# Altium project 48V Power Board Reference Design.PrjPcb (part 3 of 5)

## Sheet Motor Drivers.SchDoc
size 431 x 279 mm; Date: Not shown in title block; ApprovedBy: Not shown in title block; CheckedBy: Not shown in title block; Author: Not shown in title block; CompanyName: Not shown in title block; Engineer: Not shown in title block; Organization: Not shown in title block; Address1: Not shown in title block; Address2: Not shown in title block; Address3: Not shown in title block; Address4: Not shown in title block; DocumentNumber: 10; Revision: Use project parameter SCH_Rev; SheetNumber: 6; SheetTotal: 15; PageSetup: Record=PageOptions¦CenterHorizontal=True¦CenterVertical=True¦PrintScale=1.00¦XCorrection=1.00¦YCorrection=1.00¦PrintKind=0¦BorderSize=5000000¦LeftOffset=0¦BottomOffset=0¦Orientation=2¦PaperLength=1000¦PaperWidth=1000¦Scale=100¦PaperSource=15¦PrintQuality=600¦MediaType=1¦DitherType=10¦PaperKind=Letter¦PrintScaleMode=1
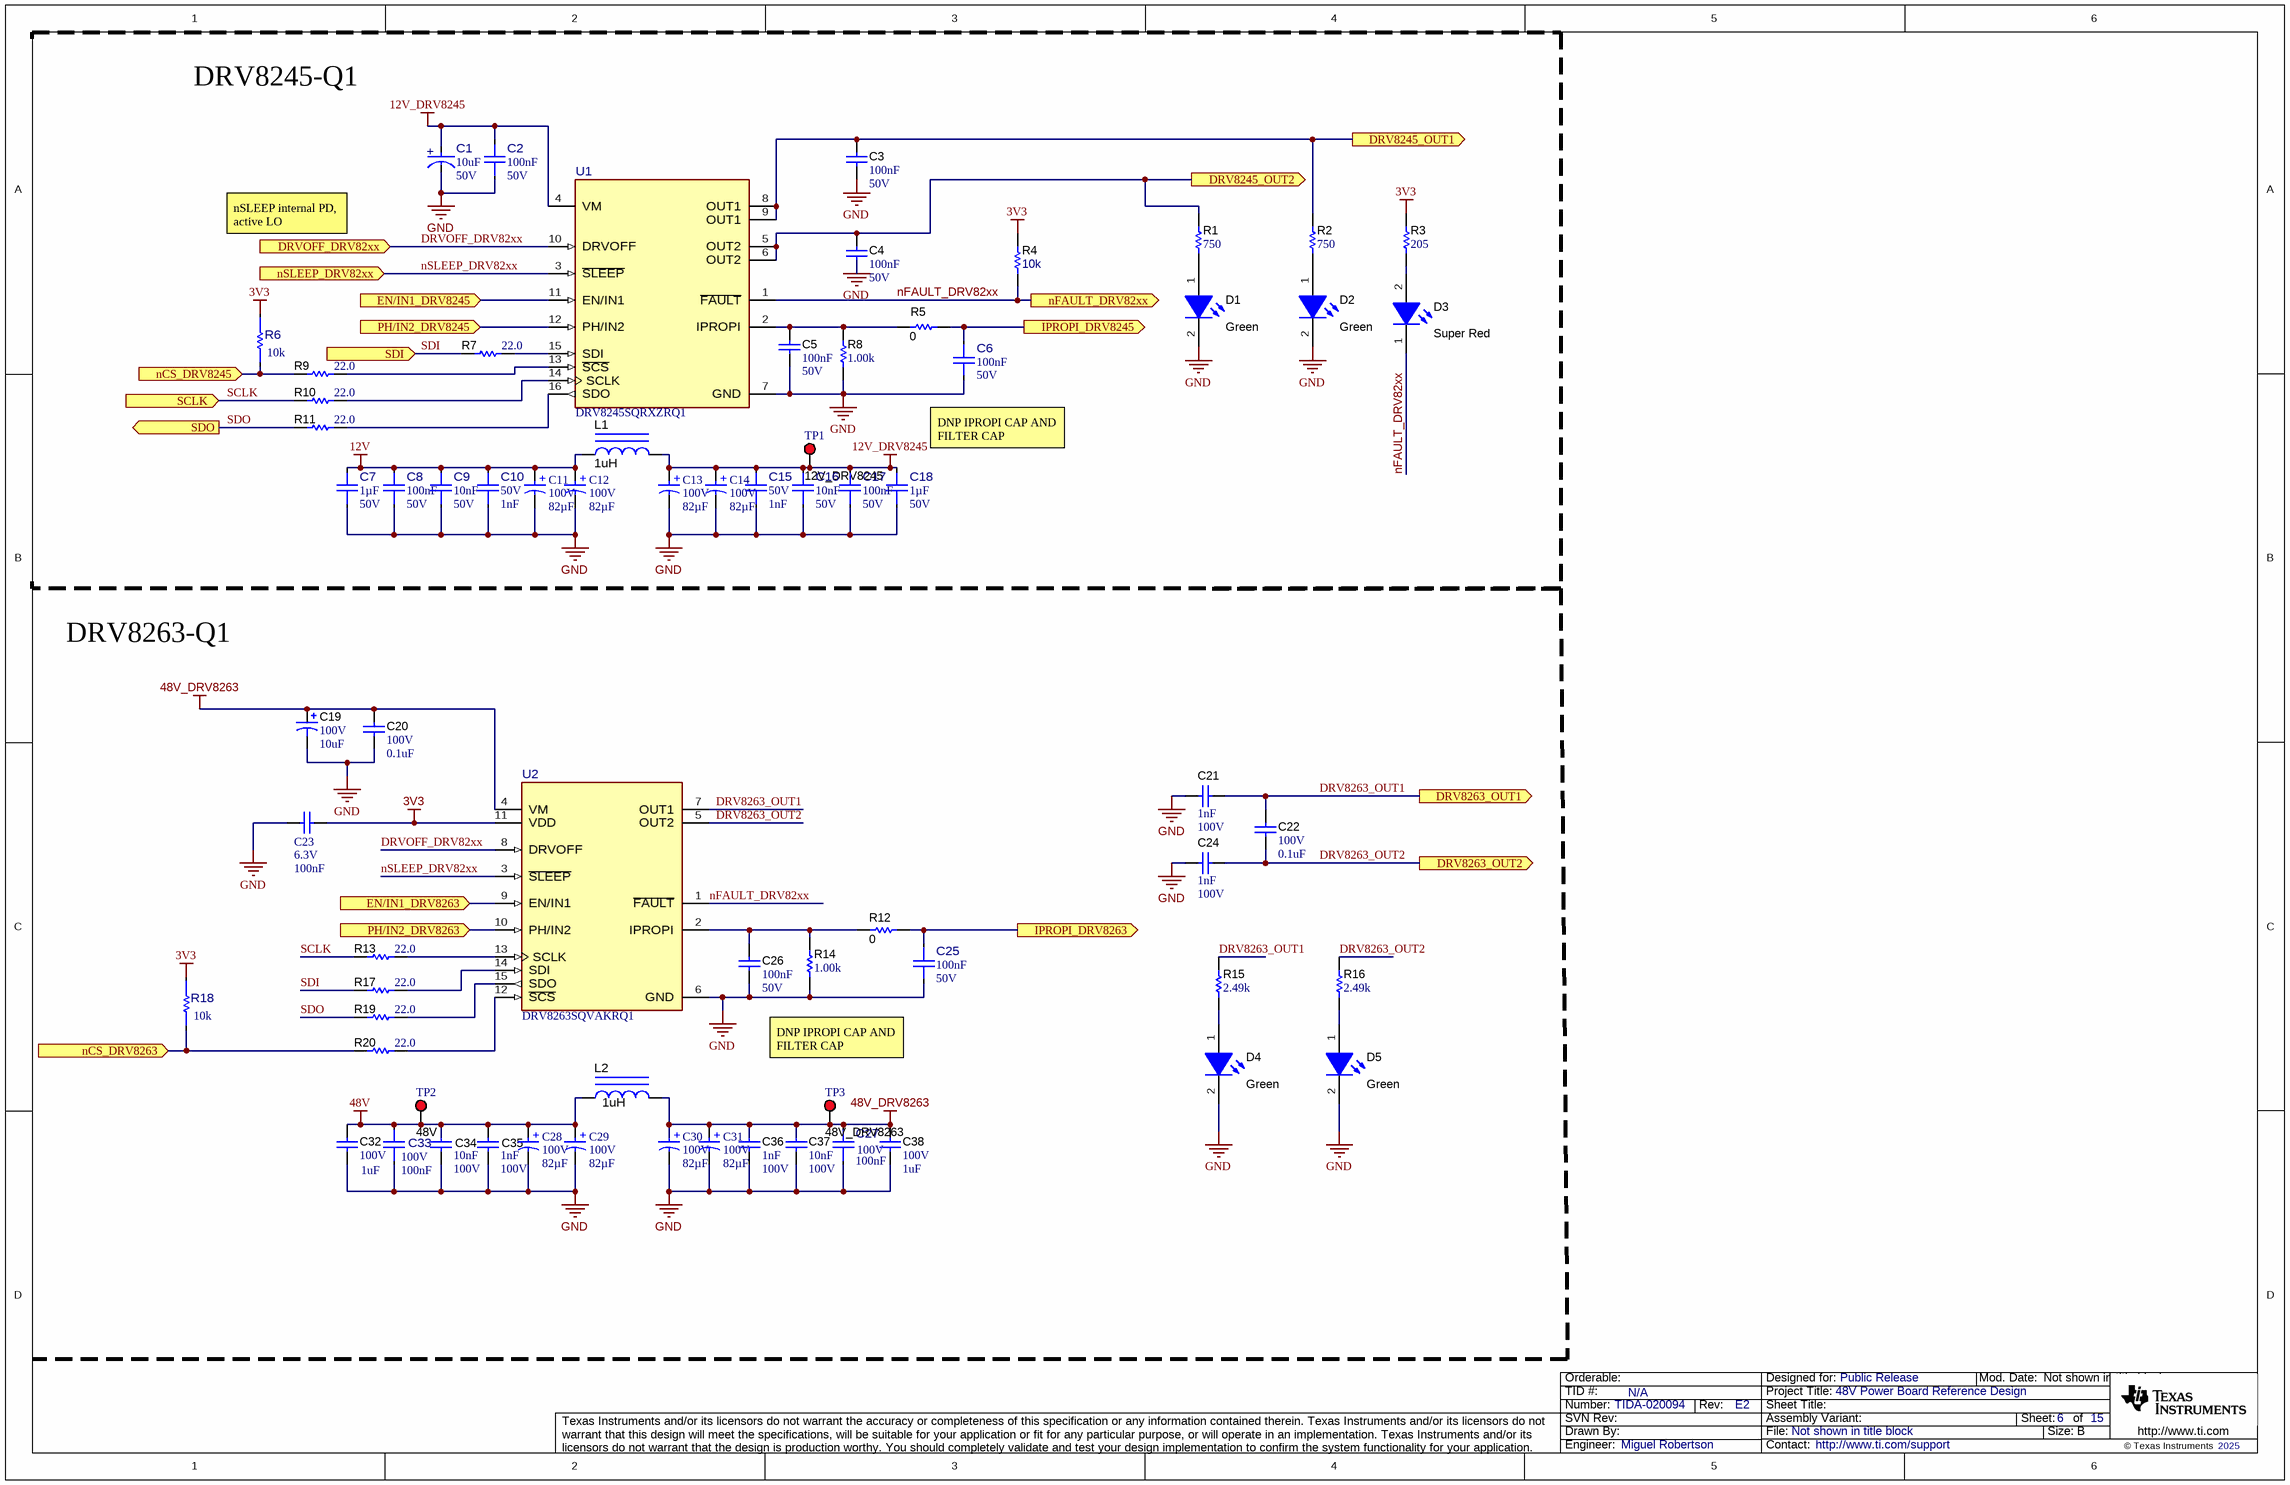
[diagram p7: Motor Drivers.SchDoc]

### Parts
C1  ValueDisplayed: 10uF  VDC_V: 50V  [FP-EEE-HA1H100P_RADIAL-MFG]  (hidden comment: EEE-HA1H100P)
C2  Cap_F: 100nF  VDC_V: 50V  [FP-06035C104J4Z2A_0603-MFG]  (hidden comment: 06035C104J4Z2A)
C3  Cap_F: 100nF  VDC_V: 50V  [0603]  (hidden comment: 885012206095)
C4  Cap_F: 100nF  VDC_V: 50V  [0603]  (hidden comment: 885012206095)
C5  Cap_F: 100nF  VDC_V: 50V  [0603]  (hidden comment: 885012206095)
C6  Cap_F: 100nF  VDC_V: 50V  [FP-C0603C104J5RAC7867_0603-MFG]  (hidden comment: C0603C104J5RAC7867)
C7  Cap_F: 1µF  VDC_V: 50V  [FP-CL10B105KB9VPJC_0603-MFG]  (hidden comment: CL10B105KB9VPJC)
C8  Cap_F: 100nF  VDC_V: 50V  [FP-06035C104J4Z2A_0603-MFG]  (hidden comment: 06035C104J4Z2A)
C9  Cap_F: 10nF  VDC_V: 50V  [FP-GCE188R71H103KA01D_0603-MFG]  (hidden comment: GCE188R71H103KA01D)
C10  VDC_V: 50V  Cap_F: 1nF  [FP-CGA3E2X7R1H102K080AA_0603-MFG]  (hidden comment: CGA3E2X7R1H102K080AA)
C11  Cap_F: 82µF  Rated Voltage (DC): 100V  [WCAP-ATUL_D10H20]  (hidden comment: 860040875004)
C12  Cap_F: 82µF  Rated Voltage (DC): 100V  [WCAP-ATUL_D10H20]  (hidden comment: 860040875004)
C13  Cap_F: 82µF  Rated Voltage (DC): 100V  [WCAP-ATUL_D10H20]  (hidden comment: 860040875004)
C14  Cap_F: 82µF  Rated Voltage (DC): 100V  [WCAP-ATUL_D10H20]  (hidden comment: 860040875004)
C15  VDC_V: 50V  Cap_F: 1nF  [FP-CGA3E2X7R1H102K080AA_0603-MFG]  (hidden comment: CGA3E2X7R1H102K080AA)
C16  Cap_F: 10nF  VDC_V: 50V  [FP-GCE188R71H103KA01D_0603-MFG]  (hidden comment: GCE188R71H103KA01D)
C17  Cap_F: 100nF  VDC_V: 50V  [FP-06035C104J4Z2A_0603-MFG]  (hidden comment: 06035C104J4Z2A)
C18  Cap_F: 1µF  VDC_V: 50V  [FP-CL10B105KB9VPJC_0603-MFG]  (hidden comment: CL10B105KB9VPJC)
C19  VDC_V: 100V  ValueDisplayed: 10uF  [SM_RADIAL_E]  (hidden comment: EEE-2AA100UP)
C20  VDC_V: 100V  ValueDisplayed: 0.1uF  [1206_180]  (hidden comment: C3216X7R2A104K160AA)
C21  Cap_F: 1nF  VDC_V: 100V  [0603]  (hidden comment: CGA3E2X7R2A102K080AA)
C22  VDC_V: 100V  ValueDisplayed: 0.1uF  [1206_180]  (hidden comment: C3216X7R2A104K160AA)
C23  Cap_F: 100nF  Rated Voltage (DC): 6.3V  [WCAP-CSGP_0402_L1W0.5H0.5]  (hidden comment: 885012105001)
C24  Cap_F: 1nF  VDC_V: 100V  [0603]  (hidden comment: CGA3E2X7R2A102K080AA)
C25  Cap_F: 100nF  VDC_V: 50V  [FP-C0603C104J5RAC7867_0603-MFG]  (hidden comment: C0603C104J5RAC7867)
C26  Cap_F: 100nF  VDC_V: 50V  [0603]  (hidden comment: 885012206095)
C27  VDC_V: 100V  Cap_F: 100nF  [FP-885012206120_0603-MFG]  (hidden comment: 885012206120)
C28  Cap_F: 82µF  Rated Voltage (DC): 100V  [WCAP-ATUL_D10H20]  (hidden comment: 860040875004)
C29  Cap_F: 82µF  Rated Voltage (DC): 100V  [WCAP-ATUL_D10H20]  (hidden comment: 860040875004)
C30  Cap_F: 82µF  Rated Voltage (DC): 100V  [WCAP-ATUL_D10H20]  (hidden comment: 860040875004)
C31  Cap_F: 82µF  Rated Voltage (DC): 100V  [WCAP-ATUL_D10H20]  (hidden comment: 860040875004)
C32  VDC_V: 100V  ValueDisplayed: 1uF  [0805_HV]  (hidden comment: C2012X7S2A105K125AB)
C33  VDC_V: 100V  Cap_F: 100nF  [FP-885012206120_0603-MFG]  (hidden comment: 885012206120)
C34  Cap_F: 10nF  VDC_V: 100V  [0603]  (hidden comment: 885012206114)
C35  Cap_F: 1nF  VDC_V: 100V  [0603]  (hidden comment: 06031C102KAT2A)
C36  Cap_F: 1nF  VDC_V: 100V  [0603]  (hidden comment: 06031C102KAT2A)
C37  Cap_F: 10nF  VDC_V: 100V  [0603]  (hidden comment: 885012206114)
C38  VDC_V: 100V  ValueDisplayed: 1uF  [0805_HV]  (hidden comment: C2012X7S2A105K125AB)
D1  value Green  [LTST-C191_Green]  (hidden comment: LTST-C191KGKT)
D2  value Green  [LTST-C191_Green]  (hidden comment: LTST-C191KGKT)
D3  value Super Red  [WL-SMCW_RED]  (hidden comment: 150060SS75000)
D4  value Green  [LTST-C191_Green]  (hidden comment: LTST-C191KGKT)
D5  value Green  [LTST-C191_Green]  (hidden comment: LTST-C191KGKT)
L1  ValueDisplayed: 1uH  [WE-HCC_1210]  (hidden comment: 7443320100)
L2  ValueDisplayed: 1uH  [WE-HCC_1210]  (hidden comment: 7443320100)
R1  ValueDisplayed: 750  [0603]  (hidden comment: RC0603FR-07750RL)
R2  ValueDisplayed: 750  [0603]  (hidden comment: RC0603FR-07750RL)
R3  ValueDisplayed: 205  [0603]  (hidden comment: RC0603FR-07205RL)
R4  ValueDisplayed: 10k  [0603]  (hidden comment: RC0603JR-0710KL)
R5  value 0  [0603L]  (hidden comment: Resistor)
R6  value 10k  [FP-RC0402JR-0710KL_0402-MFG]  (hidden comment: RC0402JR-0710KL)
R7  ValueDisplayed: 22.0  [0201]  (hidden comment: RC0201FR-0722RL)
R8  ValueDisplayed: 1.00k  [0603]  (hidden comment: CRCW06031K00FKEA)
R9  ValueDisplayed: 22.0  [0201]  (hidden comment: RC0201FR-0722RL)
R10  ValueDisplayed: 22.0  [0201]  (hidden comment: RC0201FR-0722RL)
R11  ValueDisplayed: 22.0  [0201]  (hidden comment: RC0201FR-0722RL)
R12  value 0  [0603L]  (hidden comment: Resistor)
R13  ValueDisplayed: 22.0  [0201]  (hidden comment: RC0201FR-0722RL)
R14  ValueDisplayed: 1.00k  [0603]  (hidden comment: RC0603FR-071KL)
R15  ValueDisplayed: 2.49k  [0603]  (hidden comment: RC0603FR-072K49L)
R16  ValueDisplayed: 2.49k  [0603]  (hidden comment: RC0603FR-072K49L)
R17  ValueDisplayed: 22.0  [0201]  (hidden comment: RC0201FR-0722RL)
R18  value 10k  [FP-RC0402JR-0710KL_0402-MFG]  (hidden comment: RC0402JR-0710KL)
R19  ValueDisplayed: 22.0  [0201]  (hidden comment: RC0201FR-0722RL)
R20  ValueDisplayed: 22.0  [0201]  (hidden comment: RC0201FR-0722RL)
TP1  12V_DRV8245  [Keystone5010]
TP2  48V  [Keystone5010]
TP3  48V_DRV8263  [Keystone5010]
U1  DRV8245SQRXZRQ1  [RXZ0016A-MFG]
U2  DRV8263SQVAKRQ1  [VAK0015A-MFG]

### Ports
DRV8245_OUT1 (out), DRV8245_OUT2 (out), DRV8263_OUT1 (out), DRV8263_OUT2 (out), DRVOFF_DRV82xx (in), EN/IN1_DRV8245 (in), EN/IN1_DRV8263 (in), IPROPI_DRV8245 (out), IPROPI_DRV8263 (out), nCS_DRV8245 (in), nCS_DRV8263 (in), nFAULT_DRV82xx (out), nSLEEP_DRV82xx (in), PH/IN2_DRV8245 (in), PH/IN2_DRV8263 (in), SCLK (in), SDI (in), SDO (out)

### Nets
3V3: C23.1 R3.2 R4.2 R6.1 R18.1 U2.11(VDD)
12V: C7.2 C8.2 C9.2 C10.2 C11.1(P) C12.1(P) L1.1
12V_DRV8245: C1.2(ANODE) C2.2 C13.1(P) C14.1(P) C15.2 C16.2 C17.2 C18.2 L1.2 TP1.1 U1.4(VM)
48V: C28.1(P) C29.1(P) C32.2 C33.2 C34.2 C35.1 L2.1 TP2.1
48V_DRV8263: C19.1(+) C20.1 C27.2 C30.1(P) C31.1(P) C36.1 C37.2 C38.2 L2.2 TP3.1 U2.4(VM)
GND: C1.1(CATHODE) C2.1 C3.1 C4.1 C5.1 C6.2 C7.1 C8.1 C9.1 C10.1 C11.2(N) C12.2(N) C13.2(N) C14.2(N) C15.1 C16.1 C17.1 C18.1 C19.2(-) C20.2 C21.1 C23.2 C24.1 C25.2 C26.1 C27.1 C28.2(N) C29.2(N) C30.2(N) C31.2(N) C32.1 C33.1 C34.1 C35.2 C36.2 C37.1 C38.1 D1.2(K) D2.2(K) D4.2(K) D5.2(K) R8.1 R14.1 U1.7(GND) U2.6(GND)
DRV8245_OUT1: C3.2 R2.2 U1.8(OUT1) U1.9(OUT1) ; port DRV8245_OUT1
DRV8245_OUT2: C4.2 R1.2 U1.5(OUT2) U1.6(OUT2) ; port DRV8245_OUT2
DRV8263_OUT1: C21.2 C22.1 R15.2 U2.7(OUT1) ; port DRV8263_OUT1
DRV8263_OUT2: C22.2 C24.2 R16.2 U2.5(OUT2) ; port DRV8263_OUT2
DRVOFF_DRV82xx: U1.10(DRVOFF) U2.8(DRVOFF) ; port DRVOFF_DRV82xx
EN/IN1_DRV8245: U1.11(EN/IN1) ; port EN/IN1_DRV8245
EN/IN1_DRV8263: U2.9(EN/IN1) ; port EN/IN1_DRV8263
IPROPI_DRV8245: C6.1 R5.2 ; port IPROPI_DRV8245
IPROPI_DRV8263: C25.1 R12.2 ; port IPROPI_DRV8263
nCS_DRV8245: R6.2 R9.1 ; port nCS_DRV8245
nCS_DRV8263: R18.2 R20.1 ; port nCS_DRV8263
nFAULT_DRV82xx: D3.1(K) R4.1 U1.1(~{FAULT}) U2.1(~{FAULT}) ; port nFAULT_DRV82xx
nSLEEP_DRV82xx: U1.3(~{SLEEP}) U2.3(~{SLEEP}) ; port nSLEEP_DRV82xx
PH/IN2_DRV8245: U1.12(PH/IN2) ; port PH/IN2_DRV8245
PH/IN2_DRV8263: U2.10(PH/IN2) ; port PH/IN2_DRV8263
SCLK: R10.1 R13.1 ; port SCLK
SDI: R7.1 R17.1 ; port SDI  [project net ]
SDO: R11.1 R19.1 ; port SDO
NetC5_2: C5.2 R5.1 R8.2 U1.2(IPROPI)
NetC26_2: C26.2 R12.1 R14.2 U2.2(IPROPI)
NetD1_1: D1.1(A) R1.1
NetD2_1: D2.1(A) R2.1
NetD3_2: D3.2(A) R3.1
NetD4_1: D4.1(A) R15.1
NetD5_1: D5.1(A) R16.1
NetR7_2: R7.2 U1.15(SDI)
NetR9_2: R9.2 U1.13(~{SCS})
NetR10_2: R10.2 U1.14(SCLK)
NetR11_2: R11.2 U1.16(SDO)
NetR13_2: R13.2 U2.13(SCLK)
NetR17_2: R17.2 U2.14(SDI)
NetR19_2: R19.2 U2.15(SDO)
NetR20_2: R20.2 U2.12(~{SCS})

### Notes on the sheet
- DRV8245-Q1
- nSLEEP internal PD, active LO
- DNP IPROPI CAP AND FILTER CAP
- DRV8263-Q1

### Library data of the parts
C1 = CMP-0094833-1: 10 µF 50 V Aluminum Electrolytic Capacitors Radial, Can - SMD - 1000 Hrs @ 105°C; Manufacturer: Panasonic Electronic Components; AEC Grade: Grade 2; IRMS_A: 35mA; SizeZ_mm: 5.5mm; Leakage Current: 5uA; Tolerance_%: 20%; Dissipation Factor: 12%; Value: 10µF; Life: 1000Hours; AEC Qualified: Yes
C2 C8 C17 = CMP-0094511-1: 0.1 µF ±5% 50V Ceramic Capacitor X7R 0603 (1608 Metric); Manufacturer: KYOCERA AVX; AEC Qualified: Yes; AEC Grade: NA; ValueDisplayed: 0.1uF; Value: 100nF; TempCo: 15%; SizeZ_mm: 0.9mm
C3-C5 C26 = CMP-0006837-2: CAP, CERM, 0.1 uF, 50 V, +/- 10%, X7R, 0603; Manufacturer: Wurth Elektronik; TaMin_C: -55°C; Polarized: N; SizeAreaWB_mm2: 4.68; Value1: Unknown; U/M: EA; Value: 0.1uF; TaMax_C: 125°C; SizeZ_mm: 1; SizeX_mm: 1.6; SizeY_mm: 0.8; SizeArea_mm2: 1.28; AEC Category: Q200
C6 C25 = CMP-0122528-1: Cap Ceramic 0.1uF 50V X7R 5% SMD 1.6 x 0.8 mm 125 C Paper T/R; Manufacturer: KEMET; AEC Qualified: No; SizeZ_mm: 0.95mm; TempCo: 15%; Value: 100nF
C7 C18 = CMP-0122257-1: 1 µF ±10% 50V Ceramic Capacitor X7R 0603 (1608 Metric); Manufacturer: Samsung; AEC Grade: Grade 1; AEC Qualified: Yes; SizeZ_mm: 1mm; TempCo: 15%; ValueDisplayed: 1uF; Value: 1µF
C9 C16 = CMP-0095668-2: Ceramic Capacitor 10nF ±10% 50V X7R 0603; Manufacturer: Murata; SizeZ_mm: 0.9mm; TempCo: 15%; AEC Grade: Grade 1; AEC Qualified: Yes
C10 C15 = CMP-0094874-1: Cap Ceramic 1nF 50V X7R 10% Pad SMD 0603 +125°C Automotive T/R; Manufacturer: TDK; Tolerance_%: 0.1%; AEC Qualified: Yes; SizeZ_mm: 1.1mm; AEC Grade: Grade 1; TempCo: 0.15
C11-C14 C28-C31 = CMP-0102582-1: WCAP-ATUL Aluminum Electrolytic Capacitor, Radial, THT, D10 x H20mm, 82µF, 100V; Manufacturer: Wurth Elektronik; Capacitance Tolerance: 20%; Dissipation Factor: 9%; Endurance: 7000h; Leakage Current: 82uA; Ripple Current: 600mA; Technical Reference: ATDF200820M100DSPAAG000
C19 = CMP-0011164-2: CAP, AL, 10 uF, 100 V, +/- 20%, AEC-Q200 Grade 3, SMD; Manufacturer: Panasonic; TaMin_C: -40°C; Polarized: Y; SizeAreaWB_mm2: 118.45; Value1: Unknown; U/M: EA; Value: 10uF; TaMax_C: 85°C; SizeZ_mm: 6.2; SizeX_mm: 9.5; SizeY_mm: 8.3; Cap_Case: 8.0x6.0mm; SizeArea_mm2: 78.85; CompType: Capacitor; Cap_F: 10µF; IRMS_A: 50mA; AEC Grade: 3; AEC Category: Q200
C20 C22 = CMP-0008709-2: CAP, CERM, 0.1 uF, 100 V, +/- 10%, X7R, 1206; Manufacturer: TDK; TaMin_C: -55°C; ESR_ohm: 30.343m; Polarized: N; SizeAreaWB_mm2: 10.92; Value1: 0.030343 ohm; U/M: EA; Value: 0.1uF; TaMax_C: 125°C; SizeZ_mm: 1.8; SizeX_mm: 3.2; SizeY_mm: 1.6; SizeArea_mm2: 5.12; Cap_F: 100nF; IRMS_A: 1.338A; AEC Category: Q200
C21 C24 = CMP-0007081-4: CAP, CERM, 1000 pF, 100 V, +/- 10%, X7R, AEC-Q200 Grade 1, 0603; Manufacturer: TDK; TaMin_C: -55°C; ESR_ohm: 1.97137; Polarized: N; SizeAreaWB_mm2: 4.68; Value1: 1.97137 ohm; U/M: EA; Value: 1000pF; TaMax_C: 125°C; SizeZ_mm: 1; SizeX_mm: 1.6; SizeY_mm: 0.8; SizeArea_mm2: 1.28; AEC Qualified: Y; IRMS_A: 305.705mA; AEC Category: Q200
C23 = CMP-0115207-1: WCAP-CSGP Multilayer Ceramic Chip Capacitor, General Purpose, size 0402, X5R, 100nF, 6.3VDC; Manufacturer: Wurth Elektronik; Capacitance Tolerance: +/-20%; Dissipation Factor: 10%; Insulation Resistance: 1GOhm; Technical Reference: X5R0402104M6R3DFCT10000
C27 C33 = CMP-0097294-1: 0.1 µF ±10% 100V Ceramic Capacitor X7R 0603 (1608 Metric); Manufacturer: Wurth Electronics; TempCo: 15%; SizeZ_mm: 0.87mm; Value: 100nF; AEC Qualified: No
C32 C38 = CMP-0007891-2: CAP, CERM, 1 uF, 100 V, +/- 10%, X7S, 0805; Manufacturer: TDK; TaMin_C: -55°C; ESR_ohm: 8.255m; Polarized: N; SizeAreaWB_mm2: 6.75; Value1: 0.008255 ohm; U/M: EA; Value: 1uF; TaMax_C: 125°C; SizeZ_mm: 1.45; SizeX_mm: 2; SizeY_mm: 1.25; Cap_Case: 0805; SizeArea_mm2: 2.5; Cap_F: 1µF; IRMS_A: 2.27442A; AEC Category: Q200
C34 C37 = CMP-0079993-1: CAP, CERM, 0.01 µF, 100 V,+/- 10%, X7R, 0603; Manufacturer: Wurth Elektronik; TaMin_C: -55°C; Polarized: N; SizeAreaWB_mm2: 4.68; U/M: EA; Value: 0.01uF; TaMax_C: 105°C; SizeZ_mm: 1; SizeX_mm: 1.6; SizeY_mm: 0.8; SizeArea_mm2: 1.28; AEC Category: Q200; ValueDisplayed: 0.01µF
C35 C36 = CMP-0006724-5: CAP, CERM, 1000 pF, 100 V, +/- 10%, X7R, 0603; Manufacturer: AVX; TaMin_C: -55°C; ESR_ohm: 2.76d; Polarized: N; SizeAreaWB_mm2: 4.68; Value1: 0.276 ohm; U/M: EA; Value: 1000pF; TaMax_C: 125°C; SizeZ_mm: 1; SizeX_mm: 1.6; SizeY_mm: 0.8; SizeArea_mm2: 1.28; AEC Category: Q200
D1 D2 D4 D5 = CMP-0078478-1: LED, Green, SMD; Manufacturer: Lite-On; Io_A: 30mA; Power_TotalModule: 75mW; Green_Lifecycle: Not Set; Vr_V: 5V; Tjmax_C: 85°C; Green_REACh: Incomplete; Value1: 0.075W; Angle: 130; Ir_A: 10µA; Vf_V: 2V; Type: AlInGaP
D3 = CMP-0002893-1: LED, Super Red, SMD; Manufacturer: Wurth Elektronik; Io_A: 20mA; Value1: W; U/M: EA; Vf_V: 1.9V; Type: AlInGaP
L1 L2 = CMP-0063986-1: Inductor, Shielded Drum Core, Ferrite, 1 uH, 24 A, 0.0012 ohm, SMD; Manufacturer: Wurth Elektronik; Isat: 32A @ 30% inductance drop; Irms: 24A @ 50C rise; Green_Lifecycle: Active; SizeAreaWB_mm2: 188.94; DCR_ohm: 1.2m; Green_REACh: Passed; Value: 1uH; Imax_A: 24A; SizeZ_mm: 10; SizeX_mm: 12.1; SizeY_mm: 11.4; SizeArea_mm2: 137.94; Ind_H: 1µH; AEC Category: Q200
R1 R2 = CMP-0023266-5: RES, 750, 1%, 0.1 W, 0603; Manufacturer: Yageo; Power_W: 100mW; TempCo: 100 ppm/C; Value_Code: 750R; Value: 750; EIA_Code: E96; SizeX_mm: 1.6; SizeY_mm: 0.8; SizeZ_mm: 1; Value2: 0.1W; SizeArea_mm2: 1.28; AEC Qualified: N; VDC_V: 75V; AEC Category: Q200; SizeAreaWB_mm2: 4.68
R3 = CMP-0022904-5: RES, 205, 1%, 0.1 W, 0603; Manufacturer: Yageo; Power_W: 100mW; TempCo: 100 ppm/C; Value_Code: 205R; Value: 205; EIA_Code: E96; SizeX_mm: 1.6; SizeY_mm: 0.8; SizeZ_mm: 1; Value2: 0.1W; SizeArea_mm2: 1.28; AEC Qualified: N; VDC_V: 75V; AEC Category: Q200; SizeAreaWB_mm2: 4.68
R4 = CMP-0025886-3: RES, 10 k, 5%, 0.1 W, 0603; Manufacturer: Yageo America; Power_W: 100mW; TempCo: 100 ppm/C; Value_Code: 10k0; U/M: EA; Value: 10k; EIA_Code: E24; SizeX_mm: 1.6; SizeY_mm: 0.8; SizeZ_mm: 1; Value2: 0.1W; SizeArea_mm2: 1.28; VDC_V: 50V; AEC Category: Q200
R5 R12 = CMP-0025697-4: RES, 0, 5%, 0.1 W, AEC-Q200 Grade 0, 0603; PartNumber: CRCW06030000Z0EA; Manufacturer: Vishay-Dale; Value_Code: 0000; Power_W: 100mW; Value2: 0.1W; VDC_V: 75V; TempCo: 200 ppm/C; EIA_Code: E24; AEC Category: Q200; AEC Qualified: Y; SizeArea_mm2: 1.28; SizeX_mm: 1.6; SizeY_mm: 0.8; SizeZ_mm: 1
R6 R18 = CMP-0094798-1: Res Thick Film 0402 10K Ohm 5% 0.063W(1/16W) ±100ppm/C Pad SMD T/R; Manufacturer: YAGEO; AEC Qualified: No; Category Cd01000Bfc2916C6: Single Components; SizeZ_mm: 0.4mm; VDC_V: 50V; Category 5C6A91606D4187Ad: Resistors; TempCo: 100ppm/°C; Power_W: 63mW; Category 7542B8484461Ae85: Passive Components
R7 R9-R11 R13 R17 R19 R20 = CMP-0027500-1: RES, 22.0, 1%, 0.05 W, 0201; Manufacturer: Yageo America; Power_W: 50mW; TempCo: 200 ppm/C; Value_Code: 22R0; U/M: EA; Value: 22.0; Res_ohm: 22; SizeX_mm: 0.6; SizeY_mm: 0.3; SizeZ_mm: 0.26; Value2: 0.05W; SizeArea_mm2: 0.18; AEC Qualified: N; VDC_V: 25V; AEC Category: Q200
R8 = CMP-0022109-5: RES, 1.00 k, 1%, 0.1 W, AEC-Q200 Grade 0, 0603; Manufacturer: Vishay-Dale; Power_W: 100mW; TempCo: 100 ppm/C; Value_Code: 1k00; Value: 1.00k; EIA_Code: E96; Res_ohm: 1k; SizeX_mm: 1.6; SizeY_mm: 0.8; SizeZ_mm: 1; Value2: 0.1W; SizeArea_mm2: 1.28; AEC Qualified: Y; VDC_V: 75V; AEC Category: Q200; AEC Grade: 0
R14 = CMP-0022895-5: RES, 1.00 k, 1%, 0.1 W, 0603; Manufacturer: Yageo; Power_W: 100mW; TempCo: 100 ppm/C; Value_Code: 1k00; Value: 1.00k; EIA_Code: E96; Res_ohm: 1k; SizeX_mm: 1.6; SizeY_mm: 0.8; SizeZ_mm: 1; Value2: 0.1W; SizeArea_mm2: 1.28; AEC Qualified: N; VDC_V: 75V; AEC Category: Q200; SizeAreaWB_mm2: 4.68
R15 R16 = CMP-0022990-5: RES, 2.49 k, 1%, 0.1 W, 0603; Manufacturer: Yageo; Power_W: 100mW; TempCo: 100 ppm/C; Value_Code: 2k49; Value: 2.49k; EIA_Code: E96; SizeX_mm: 1.6; SizeY_mm: 0.8; SizeZ_mm: 1; Value2: 0.1W; SizeArea_mm2: 1.28; AEC Qualified: N; VDC_V: 75V; AEC Category: Q200; SizeAreaWB_mm2: 4.68
TP1-TP3 = CMP-0055147-2: Test Point, Multipurpose, Red, TH; Manufacturer: Keystone Electronics; CT: TRUE; ContactFinish: Silver; Green_Lifecycle: Active; CNHeader: FALSE; Green_REACh: Passed
U1 = CMP-0095863-1: Automotive H-Bridge Driver with Integrated Current Sense and Diagnostics; Manufacturer: Texas Instruments; Max Supply Voltage: 35V; Number Of Outputs: 2; Min Supply Voltage: 4.5V; TaMax_C: +125°C; AEC Qualified: Yes; TJmax_C: +150°C; Nominal Supply Current: 10mA; Switching Frequency: 25kHz; Standoff Height: 0mm; SizeZ_mm: 1mm; AEC Grade: Grade 1; TaMin_C: -40°C
U2 = CMP-0121932-1: Automotive 65-V H-Bridge Driver with Integrated Current Sense and Diagnostics; Manufacturer: Texas Instruments; SizeZ_mm: 1mm; AEC Qualified: Yes; AEC Grade: Grade 1; Max Supply Voltage: 65V; Min Supply Voltage: 3V; Motor Type: Brushed; Nominal Supply Current: 3mA; Number Of Outputs: 2; Standoff Height: 0mm; Switching Frequency: 0-100kHz; TaMax_C: +125°C; TaMin_C: -40°C; TJmax_C: +150°C

## Sheet 12V E-Fuse.SchDoc
size 431 x 279 mm; Date: Not shown in title block; ApprovedBy: Not shown in title block; CheckedBy: Not shown in title block; Author: Not shown in title block; CompanyName: Not shown in title block; Engineer: Not shown in title block; Organization: Not shown in title block; Address1: Not shown in title block; Address2: Not shown in title block; Address3: Not shown in title block; Address4: Not shown in title block; DocumentNumber: 13; Revision: Use project parameter SCH_Rev; SheetNumber: 4; SheetTotal: 15; PageSetup: Record=PageOptions¦CenterHorizontal=True¦CenterVertical=True¦PrintScale=1.00¦XCorrection=1.00¦YCorrection=1.00¦PrintKind=0¦BorderSize=5000000¦LeftOffset=0¦BottomOffset=0¦Orientation=2¦PaperLength=1000¦PaperWidth=1000¦Scale=100¦PaperSource=15¦PrintQuality=600¦MediaType=1¦DitherType=10¦PaperKind=Letter¦PrintScaleMode=1
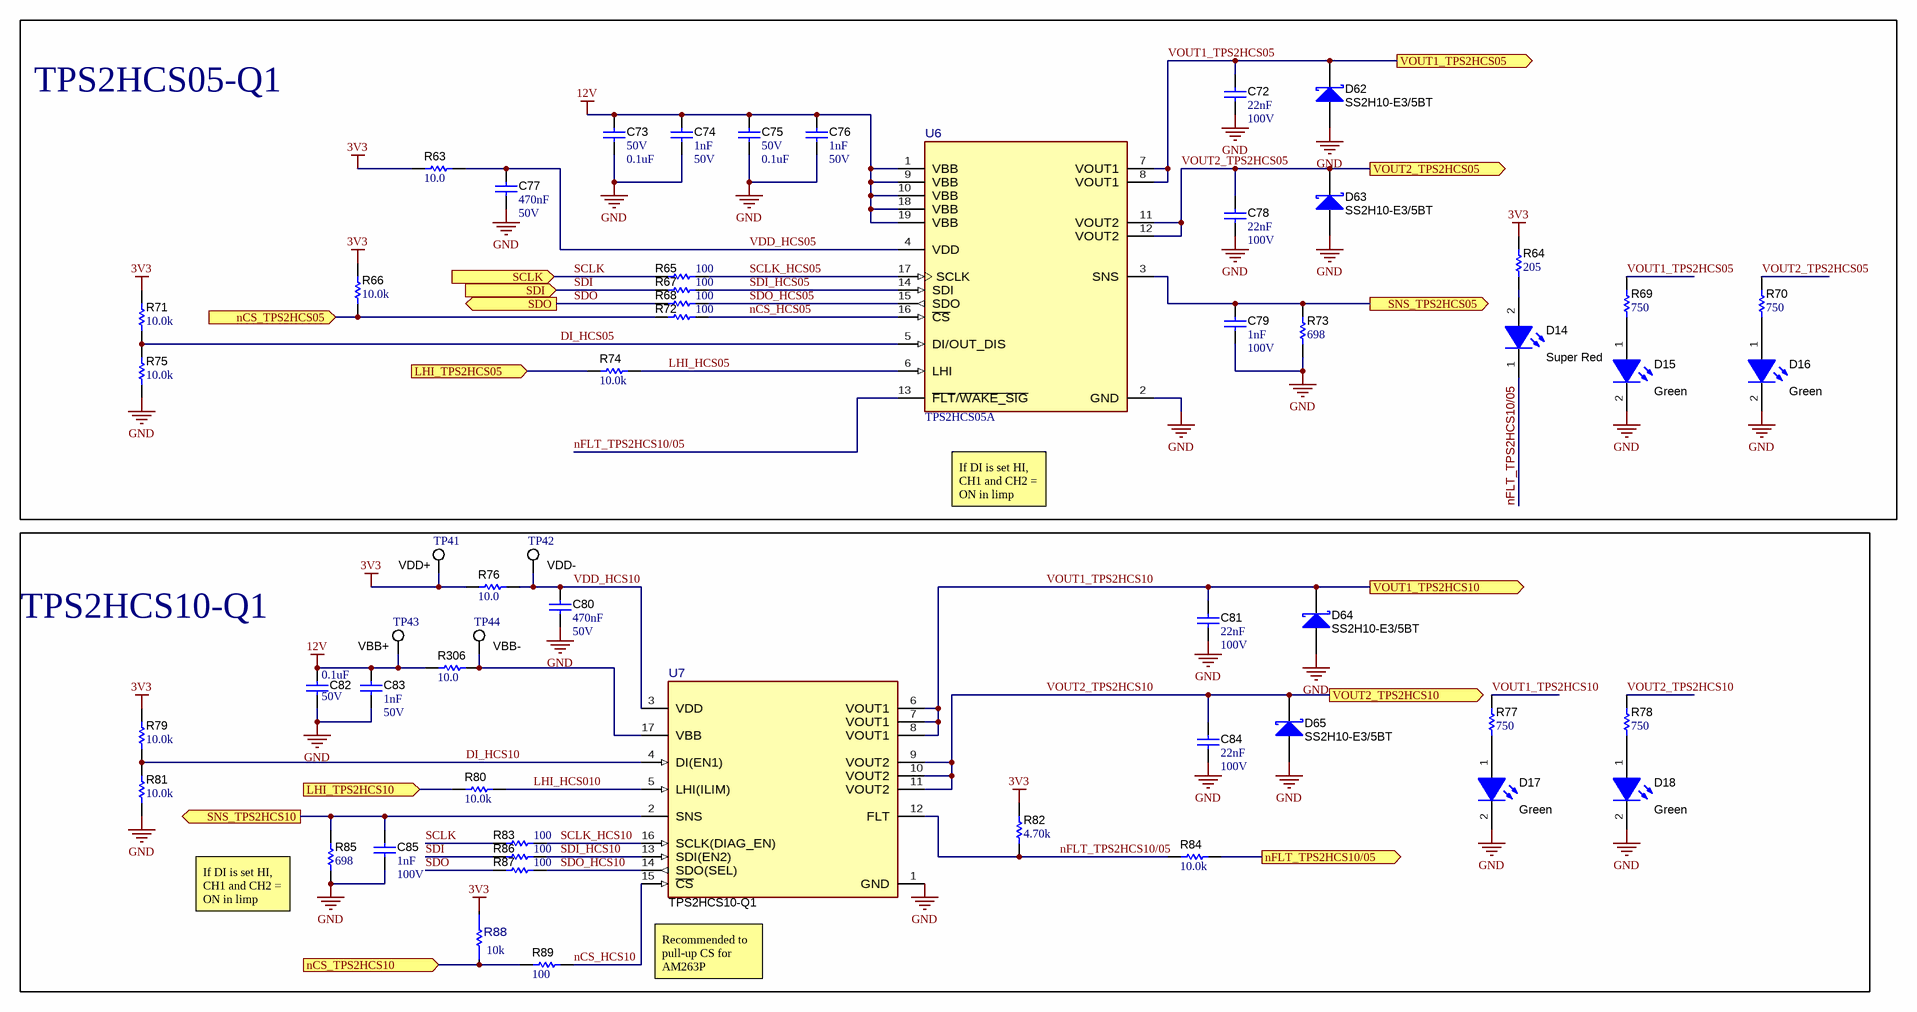
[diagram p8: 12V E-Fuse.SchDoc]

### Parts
C72  Cap_F: 22nF  VDC_V: 100V  [0603]  (hidden comment: CGA3E2X7R2A223K080AA)
C73  VDC_V: 50V  ValueDisplayed: 0.1uF  [0402]  (hidden comment: GCM155R71H104KE02D)
C74  Cap_F: 1nF  VDC_V: 50V  [0603]  (hidden comment: C0603X102K5RACTU)
C75  VDC_V: 50V  ValueDisplayed: 0.1uF  [0402]  (hidden comment: GCM155R71H104KE02D)
C76  Cap_F: 1nF  VDC_V: 50V  [0603]  (hidden comment: C0603X102K5RACTU)
C77  Cap_F: 470nF  VDC_V: 50V  [0603]  (hidden comment: C1608X7R1H474K080AC)
C78  Cap_F: 22nF  VDC_V: 100V  [0603]  (hidden comment: CGA3E2X7R2A223K080AA)
C79  Cap_F: 1nF  VDC_V: 100V  [0603]  (hidden comment: CGA3E2X7R2A102K080AA)
C80  Cap_F: 470nF  VDC_V: 50V  [0603]  (hidden comment: C1608X7R1H474K080AC)
C81  Cap_F: 22nF  VDC_V: 100V  [0603]  (hidden comment: CGA3E2X7R2A223K080AA)
C82  VDC_V: 50V  ValueDisplayed: 0.1uF  [0402]  (hidden comment: GCM155R71H104KE02D)
C83  Cap_F: 1nF  VDC_V: 50V  [0603]  (hidden comment: C0603X102K5RACTU)
C84  Cap_F: 22nF  VDC_V: 100V  [0603]  (hidden comment: CGA3E2X7R2A223K080AA)
C85  Cap_F: 1nF  VDC_V: 100V  [0603]  (hidden comment: CGA3E2X7R2A102K080AA)
D14  value Super Red  [WL-SMCW_RED]  (hidden comment: 150060SS75000)
D15  value Green  [LTST-C191_Green]  (hidden comment: LTST-C191KGKT)
D16  value Green  [LTST-C191_Green]  (hidden comment: LTST-C191KGKT)
D17  value Green  [LTST-C191_Green]  (hidden comment: LTST-C191KGKT)
D18  value Green  [LTST-C191_Green]  (hidden comment: LTST-C191KGKT)
D62  SS2H10-E3/5BT  [SMB]
D63  SS2H10-E3/5BT  [SMB]
D64  SS2H10-E3/5BT  [SMB]
D65  SS2H10-E3/5BT  [SMB]
R63  ValueDisplayed: 10.0  [0603]  (hidden comment: RC0603FR-0710RL)
R64  ValueDisplayed: 205  [0603]  (hidden comment: RC0603FR-07205RL)
R65  ValueDisplayed: 100  [0603]  (hidden comment: CRCW0603100RJNEA)
R66  ValueDisplayed: 10.0k  [0603]  (hidden comment: RMCF0603FT10K0)
R67  ValueDisplayed: 100  [0603]  (hidden comment: CRCW0603100RJNEA)
R68  ValueDisplayed: 100  [0603]  (hidden comment: CRCW0603100RJNEA)
R69  ValueDisplayed: 750  [0603]  (hidden comment: RC0603FR-07750RL)
R70  ValueDisplayed: 750  [0603]  (hidden comment: RC0603FR-07750RL)
R71  ValueDisplayed: 10.0k  [0603]  (hidden comment: RMCF0603FT10K0)
R72  ValueDisplayed: 100  [0603]  (hidden comment: CRCW0603100RJNEA)
R73  ValueDisplayed: 698  [0603]  (hidden comment: RC0603FR-07698RL)
R74  ValueDisplayed: 10.0k  [0603]  (hidden comment: RMCF0603FT10K0)
R75  ValueDisplayed: 10.0k  [0603]  (hidden comment: RMCF0603FT10K0)
R76  ValueDisplayed: 10.0  [0603]  (hidden comment: RC0603FR-0710RL)
R77  ValueDisplayed: 750  [0603]  (hidden comment: RC0603FR-07750RL)
R78  ValueDisplayed: 750  [0603]  (hidden comment: RC0603FR-07750RL)
R79  ValueDisplayed: 10.0k  [0603]  (hidden comment: RMCF0603FT10K0)
R80  ValueDisplayed: 10.0k  [0603]  (hidden comment: RMCF0603FT10K0)
R81  ValueDisplayed: 10.0k  [0603]  (hidden comment: RMCF0603FT10K0)
R82  ValueDisplayed: 4.70k  [0603]  (hidden comment: RC0603FR-074K7L)
R83  ValueDisplayed: 100  [0603]  (hidden comment: CRCW0603100RJNEA)
R84  ValueDisplayed: 10.0k  [0603]  (hidden comment: RMCF0603FT10K0)
R85  ValueDisplayed: 698  [0603]  (hidden comment: RC0603FR-07698RL)
R86  ValueDisplayed: 100  [0603]  (hidden comment: CRCW0603100RJNEA)
R87  ValueDisplayed: 100  [0603]  (hidden comment: CRCW0603100RJNEA)
R88  value 10k  [FP-RC0402JR-0710KL_0402-MFG]  (hidden comment: RC0402JR-0710KL)
R89  ValueDisplayed: 100  [0603]  (hidden comment: CRCW0603100RJNEA)
R306  ValueDisplayed: 10.0  [0603]  (hidden comment: RC0603FR-0710RL)
TP41  VDD+  [Keystone5012]
TP42  VDD-  [Keystone5012]
TP43  VBB+  [Keystone5012]
TP44  VBB-  [Keystone5012]
U6  TPS2HCS05A  [PWC0018A-MFG]
U7  TPS2HCS10-Q1  [PWP0016P-MFG]

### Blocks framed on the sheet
TPS2HCS05-Q1: C72-C79 D14-D16 D62 D63 R63-R75 U6
TPS2HCS10-Q1: C80-C85 D17 D18 D64 D65 R76-R89 R306 TP41-TP44 U7

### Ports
LHI_TPS2HCS05 (in), LHI_TPS2HCS10 (in), nCS_TPS2HCS05 (in), nCS_TPS2HCS10 (in), nFLT_TPS2HCS10/05 (out), SCLK (in), SDI (in), SDO (out), SNS_TPS2HCS05 (out), SNS_TPS2HCS10 (out), VOUT1_TPS2HCS05 (out), VOUT1_TPS2HCS10 (out), VOUT2_TPS2HCS05 (out), VOUT2_TPS2HCS10 (out)

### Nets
3V3: R63.1 R64.2 R66.2 R71.2 R76.1 R79.2 R82.2 R88.1 TP41.1
12V: C73.1 C74.1 C75.1 C76.1 C82.1 C83.1 R306.1 TP43.1 U6.1(VBB) U6.9(VBB) U6.10(VBB) U6.18(VBB) U6.19(VBB)
GND: C72.2 C73.2 C74.2 C75.2 C76.2 C77.2 C78.2 C79.2 C80.2 C81.2 C82.2 C83.2 C84.2 C85.2 D15.2(K) D16.2(K) D17.2(K) D18.2(K) D62.2(A) D63.2(A) D64.2(A) D65.2(A) R73.1 R75.2 R81.2 R85.1 U6.2(GND) U7.1(GND)
DI_HCS05: R71.1 R75.1 U6.5(DI/OUT_DIS)  [project net DI_HCS05_4]
DI_HCS10: R79.1 R81.1 U7.4(DI(EN1))  [project net DI_HCS10_4]
LHI_HCS05: R74.1 U6.6(LHI)  [project net LHI_HCS05_4]
LHI_HCS010: R80.1 U7.5(LHI(ILIM))  [project net LHI_HCS010_4]
LHI_TPS2HCS05: R74.2 ; port LHI_TPS2HCS05
LHI_TPS2HCS10: R80.2 ; port LHI_TPS2HCS10
nCS_HCS05: R72.2 U6.16(~{CS})  [project net nCS_HCS05_4]
nCS_HCS10: R89.2 U7.15(~{CS})  [project net nCS_HCS10_4]
nCS_TPS2HCS05: R66.1 R72.1 ; port nCS_TPS2HCS05
nCS_TPS2HCS10: R88.2 R89.1 ; port nCS_TPS2HCS10
nFLT_TPS2HCS10/05: D14.1(K) R82.1 R84.2 U6.13(~{FLT}/~{WAKE_SIG}) U7.12(FLT)  [project net nFLT_TPS2HCS10/05_4]
nFLT_TPS2HCS10/05: R84.1 ; port nFLT_TPS2HCS10/05  [a separate net that carries the same name]
SCLK: R65.1 R83.1 ; port SCLK
SCLK_HCS05: R65.2 U6.17(SCLK)  [project net SCLK_HCS05_4]
SCLK_HCS10: R83.2 U7.16(SCLK(DIAG_EN))  [project net SCLK_HCS10_4]
SDI: R67.1 R86.1 ; port SDI  [project net ]
SDI_HCS05: R67.2 U6.14(SDI)  [project net SDI_HCS05_4]
SDI_HCS10: R86.2 U7.13(SDI(EN2))  [project net SDI_HCS10_4]
SDO: R68.1 R87.1 ; port SDO
SDO_HCS05: R68.2 U6.15(SDO)  [project net SDO_HCS05_4]
SDO_HCS10: R87.2 U7.14(SDO(SEL))  [project net SDO_HCS10_4]
SNS_TPS2HCS05: C79.1 R73.2 U6.3(SNS) ; port SNS_TPS2HCS05
SNS_TPS2HCS10: C85.1 R85.2 U7.2(SNS) ; port SNS_TPS2HCS10
VDD_HCS05: C77.1 R63.2 U6.4(VDD)  [project net VDD_HCS05_4]
VDD_HCS10: C80.1 R76.2 TP42.1 U7.3(VDD)  [project net VDD_HCS10_4]
VOUT1_TPS2HCS05: C72.1 D62.1(K) R69.2 U6.7(VOUT1) U6.8(VOUT1) ; port VOUT1_TPS2HCS05
VOUT1_TPS2HCS10: C81.1 D64.1(K) R77.2 U7.6(VOUT1) U7.7(VOUT1) U7.8(VOUT1) ; port VOUT1_TPS2HCS10
VOUT2_TPS2HCS05: C78.1 D63.1(K) R70.2 U6.11(VOUT2) U6.12(VOUT2) ; port VOUT2_TPS2HCS05
VOUT2_TPS2HCS10: C84.1 D65.1(K) R78.2 U7.9(VOUT2) U7.10(VOUT2) U7.11(VOUT2) ; port VOUT2_TPS2HCS10
NetD14_2: D14.2(A) R64.1
NetD15_1: D15.1(A) R69.1
NetD16_1: D16.1(A) R70.1
NetD17_1: D17.1(A) R77.1
NetD18_1: D18.1(A) R78.1
NetR306_2: R306.2 TP44.1 U7.17(VBB)

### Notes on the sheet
- If DI is set HI, CH1 and CH2 = ON in limp home state
- (near R85) If DI is set HI, CH1 and CH2 = ON in limp home state
- (near U7) Recommended to pull-up CS for AM263P

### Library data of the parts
C72 C78 C81 C84 = CMP-0007086-4: CAP, CERM, 0.022 uF, 100 V, +/- 10%, X7R, AEC-Q200 Grade 1, 0603; Manufacturer: TDK; TaMin_C: -55°C; ESR_ohm: 83.542m; Polarized: N; SizeAreaWB_mm2: 4.68; Value1: 0.083542 ohm; U/M: EA; TaMax_C: 125°C; SizeZ_mm: 1; SizeX_mm: 1.6; SizeY_mm: 0.8; SizeArea_mm2: 1.28; AEC Qualified: Y; IRMS_A: 609.312mA; AEC Category: Q200
C73 C75 C82 = CMP-0006356-2: CAP, CERM, 0.1 uF, 50 V, +/- 10%, X7R, AEC-Q200 Grade 1, 0402; Manufacturer: MuRata; TaMin_C: -55°C; Polarized: N; SizeAreaWB_mm2: 3; Value1: Unknown; U/M: EA; Value: 0.1uF; TaMax_C: 125°C; SizeZ_mm: 0.6; SizeX_mm: 1; SizeY_mm: 0.5; AEC Qualified: Y; Cap_F: 100nF; AEC Category: Q200
C74 C76 C83 = CMP-0006976-5: CAP, CERM, 1000 pF, 50 V, +/- 10%, X7R, 0603; Manufacturer: Kemet; TaMin_C: -55°C; Polarized: N; SizeAreaWB_mm2: 4.68; Value1: Unknown; U/M: EA; Value: 1000pF; TaMax_C: 125°C; SizeZ_mm: 1; SizeX_mm: 1.6; SizeY_mm: 0.8; SizeArea_mm2: 1.28; AEC Category: Q200
C77 C80 = CMP-0007050-1: CAP, CERM, 0.47 uF, 50 V, +/- 10%, X7R, 0603; Manufacturer: TDK; TaMin_C: -55°C; ESR_ohm: 10.974m; Polarized: N; SizeAreaWB_mm2: 4.68; Value1: 0.010974 ohm; U/M: EA; Value: 0.47uF; TaMax_C: 125°C; SizeZ_mm: 1; SizeX_mm: 1.6; SizeY_mm: 0.8; SizeArea_mm2: 1.28; IRMS_A: 1.5748A; AEC Category: Q200
C79 C85 = CMP-0007081-4: CAP, CERM, 1000 pF, 100 V, +/- 10%, X7R, AEC-Q200 Grade 1, 0603; Manufacturer: TDK; TaMin_C: -55°C; ESR_ohm: 1.9714; Polarized: N; SizeAreaWB_mm2: 4.68; Value1: 1.97137 ohm; U/M: EA; Value: 1000pF; TaMax_C: 125°C; SizeZ_mm: 1; SizeX_mm: 1.6; SizeY_mm: 0.8; SizeArea_mm2: 1.28; AEC Qualified: Y; IRMS_A: 305.705mA; AEC Category: Q200
D14 = CMP-0002893-1: as D3 on sheet Motor Drivers
D15-D18 = CMP-0078478-1: as D1 on sheet Motor Drivers
D62-D65 = CMP-0028987-2: Diode, Schottky, 100 V, 2 A, SMB; Manufacturer: Vishay-Semiconductor; Vf_V: 790mV; AEC Qualified: N; SizeArea_mm2: 21.336; Value: 100V; SizeX_mm: 5.6; Value1: 2A; Value2: 0.79V; SizeZ_mm: 2.6; SizeAreaWB_mm2: 44.156; AEC Category: Q101; TJmax_C: 175°C; SizeY_mm: 3.81
R63 R76 R306 = CMP-0022751-4: RES, 10.0, 1%, 0.1 W, 0603; Manufacturer: Yageo; Power_W: 100mW; TempCo: 100 ppm/C; Value_Code: 10R0; Value: 10.0; EIA_Code: E96; Res_ohm: 10; SizeX_mm: 1.6; SizeY_mm: 0.8; SizeZ_mm: 1; Value2: 0.1W; SizeArea_mm2: 1.28; AEC Qualified: N; VDC_V: 75V; AEC Category: Q200; SizeAreaWB_mm2: 4.68
R64 = CMP-0022904-5: as R3 on sheet Motor Drivers
R65 R67 R68 R72 R83 R86 R87 R89 = CMP-0025700-3: RES, 100, 5%, 0.1 W, 0603; Manufacturer: Vishay-Dale; Power_W: 100mW; TempCo: 200 ppm/C; Value_Code: 100R; U/M: EA; Value: 100; EIA_Code: E24; SizeX_mm: 1.6; SizeY_mm: 0.8; SizeZ_mm: 1; Value2: 0.1W; SizeArea_mm2: 1.28; VDC_V: 75V; AEC Category: Q200
R66 R71 R74 R75 R79-R81 R84 = CMP-0023341-2: RES, 10.0 k, 1%, 0.1 W, AEC-Q200 Grade 0, 0603; Manufacturer: Stackpole Electronics Inc; Power_W: 100mW; TempCo: 100 ppm/C; Value_Code: 10k0; U/M: EA; Value: 10.0k; EIA_Code: E96; Res_ohm: 10k; SizeX_mm: 1.6; SizeY_mm: 0.8; SizeZ_mm: 1; Value2: 0.1W; SizeArea_mm2: 1.28; AEC Qualified: Y; VDC_V: 75V; AEC Grade: 0; AEC Category: Q200
R69 R70 R77 R78 = CMP-0023266-5: as R1 on sheet Motor Drivers
R73 R85 = CMP-0023243-5: RES, 698, 1%, 0.1 W, 0603; Manufacturer: Yageo; Power_W: 100mW; TempCo: 100 ppm/C; Value_Code: 698R; Value: 698; EIA_Code: E96; SizeX_mm: 1.6; SizeY_mm: 0.8; SizeZ_mm: 1; Value2: 0.1W; SizeArea_mm2: 1.28; AEC Qualified: N; VDC_V: 75V; AEC Category: Q200; SizeAreaWB_mm2: 4.68
R82 = CMP-0023153-5: RES, 4.70 k, 1%, 0.1 W, 0603; Manufacturer: Yageo; Power_W: 100mW; TempCo: 100 ppm/C; Value_Code: 4k70; Value: 4.70k; Res_ohm: 4.7k; SizeX_mm: 1.6; SizeY_mm: 0.8; SizeZ_mm: 1; Value2: 0.1W; SizeArea_mm2: 1.28; AEC Qualified: N; VDC_V: 75V; AEC Category: Q200; SizeAreaWB_mm2: 4.68
R88 = CMP-0094798-1: as R6 on sheet Motor Drivers
TP41-TP44 = CMP-0055149-1: Test Point, Multipurpose, White, TH; Manufacturer: Keystone; CNHeader: FALSE; Green_Lifecycle: Active; Green_REACh: Passed; ContactFinish: Silver; CT: TRUE
U6 = CMP-0124507-1: 5mΩ, Automotive Dual-Channel, SPI Controlled High-Side Switch with Integrated I2 t Wire Protection and low power mode; Manufacturer: Texas Instruments; SizeZ_mm: 1.2mm; AEC Qualified: Yes; AEC Grade: Grade 1; Max Supply Voltage: 18V; Min Supply Voltage: 6V; Nominal Supply Current: 2-4.9mA; Number Of Drivers: 2; Standoff Height: 0.05mm; TaMax_C: +125°C; TaMin_C: -40°C; TJmax_C: +150°C
U7 = CMP-0098417-1: Manufacturer: Texas Instruments; SizeZ_mm: 1.2mm; Standoff Height: 0.05mm

## Sheet Backbone_input2.SchDoc
size 431 x 279 mm; Date: Not shown in title block; ApprovedBy: Not shown in title block; CheckedBy: Not shown in title block; Author: Not shown in title block; CompanyName: Not shown in title block; Engineer: Not shown in title block; Organization: Not shown in title block; Address1: Not shown in title block; Address2: Not shown in title block; Address3: Not shown in title block; Address4: Not shown in title block; DocumentNumber: 4; Revision: Use project parameter SCH_Rev; SheetNumber: 3; SheetTotal: 15; PageSetup: Record=PageOptions¦CenterHorizontal=True¦CenterVertical=True¦PrintScale=1.00¦XCorrection=1.00¦YCorrection=1.00¦PrintKind=0¦BorderSize=5000000¦LeftOffset=0¦BottomOffset=0¦Orientation=2¦PaperLength=1000¦PaperWidth=1000¦Scale=100¦PaperSource=15¦PrintQuality=600¦MediaType=1¦DitherType=10¦PaperKind=Letter¦PrintScaleMode=1
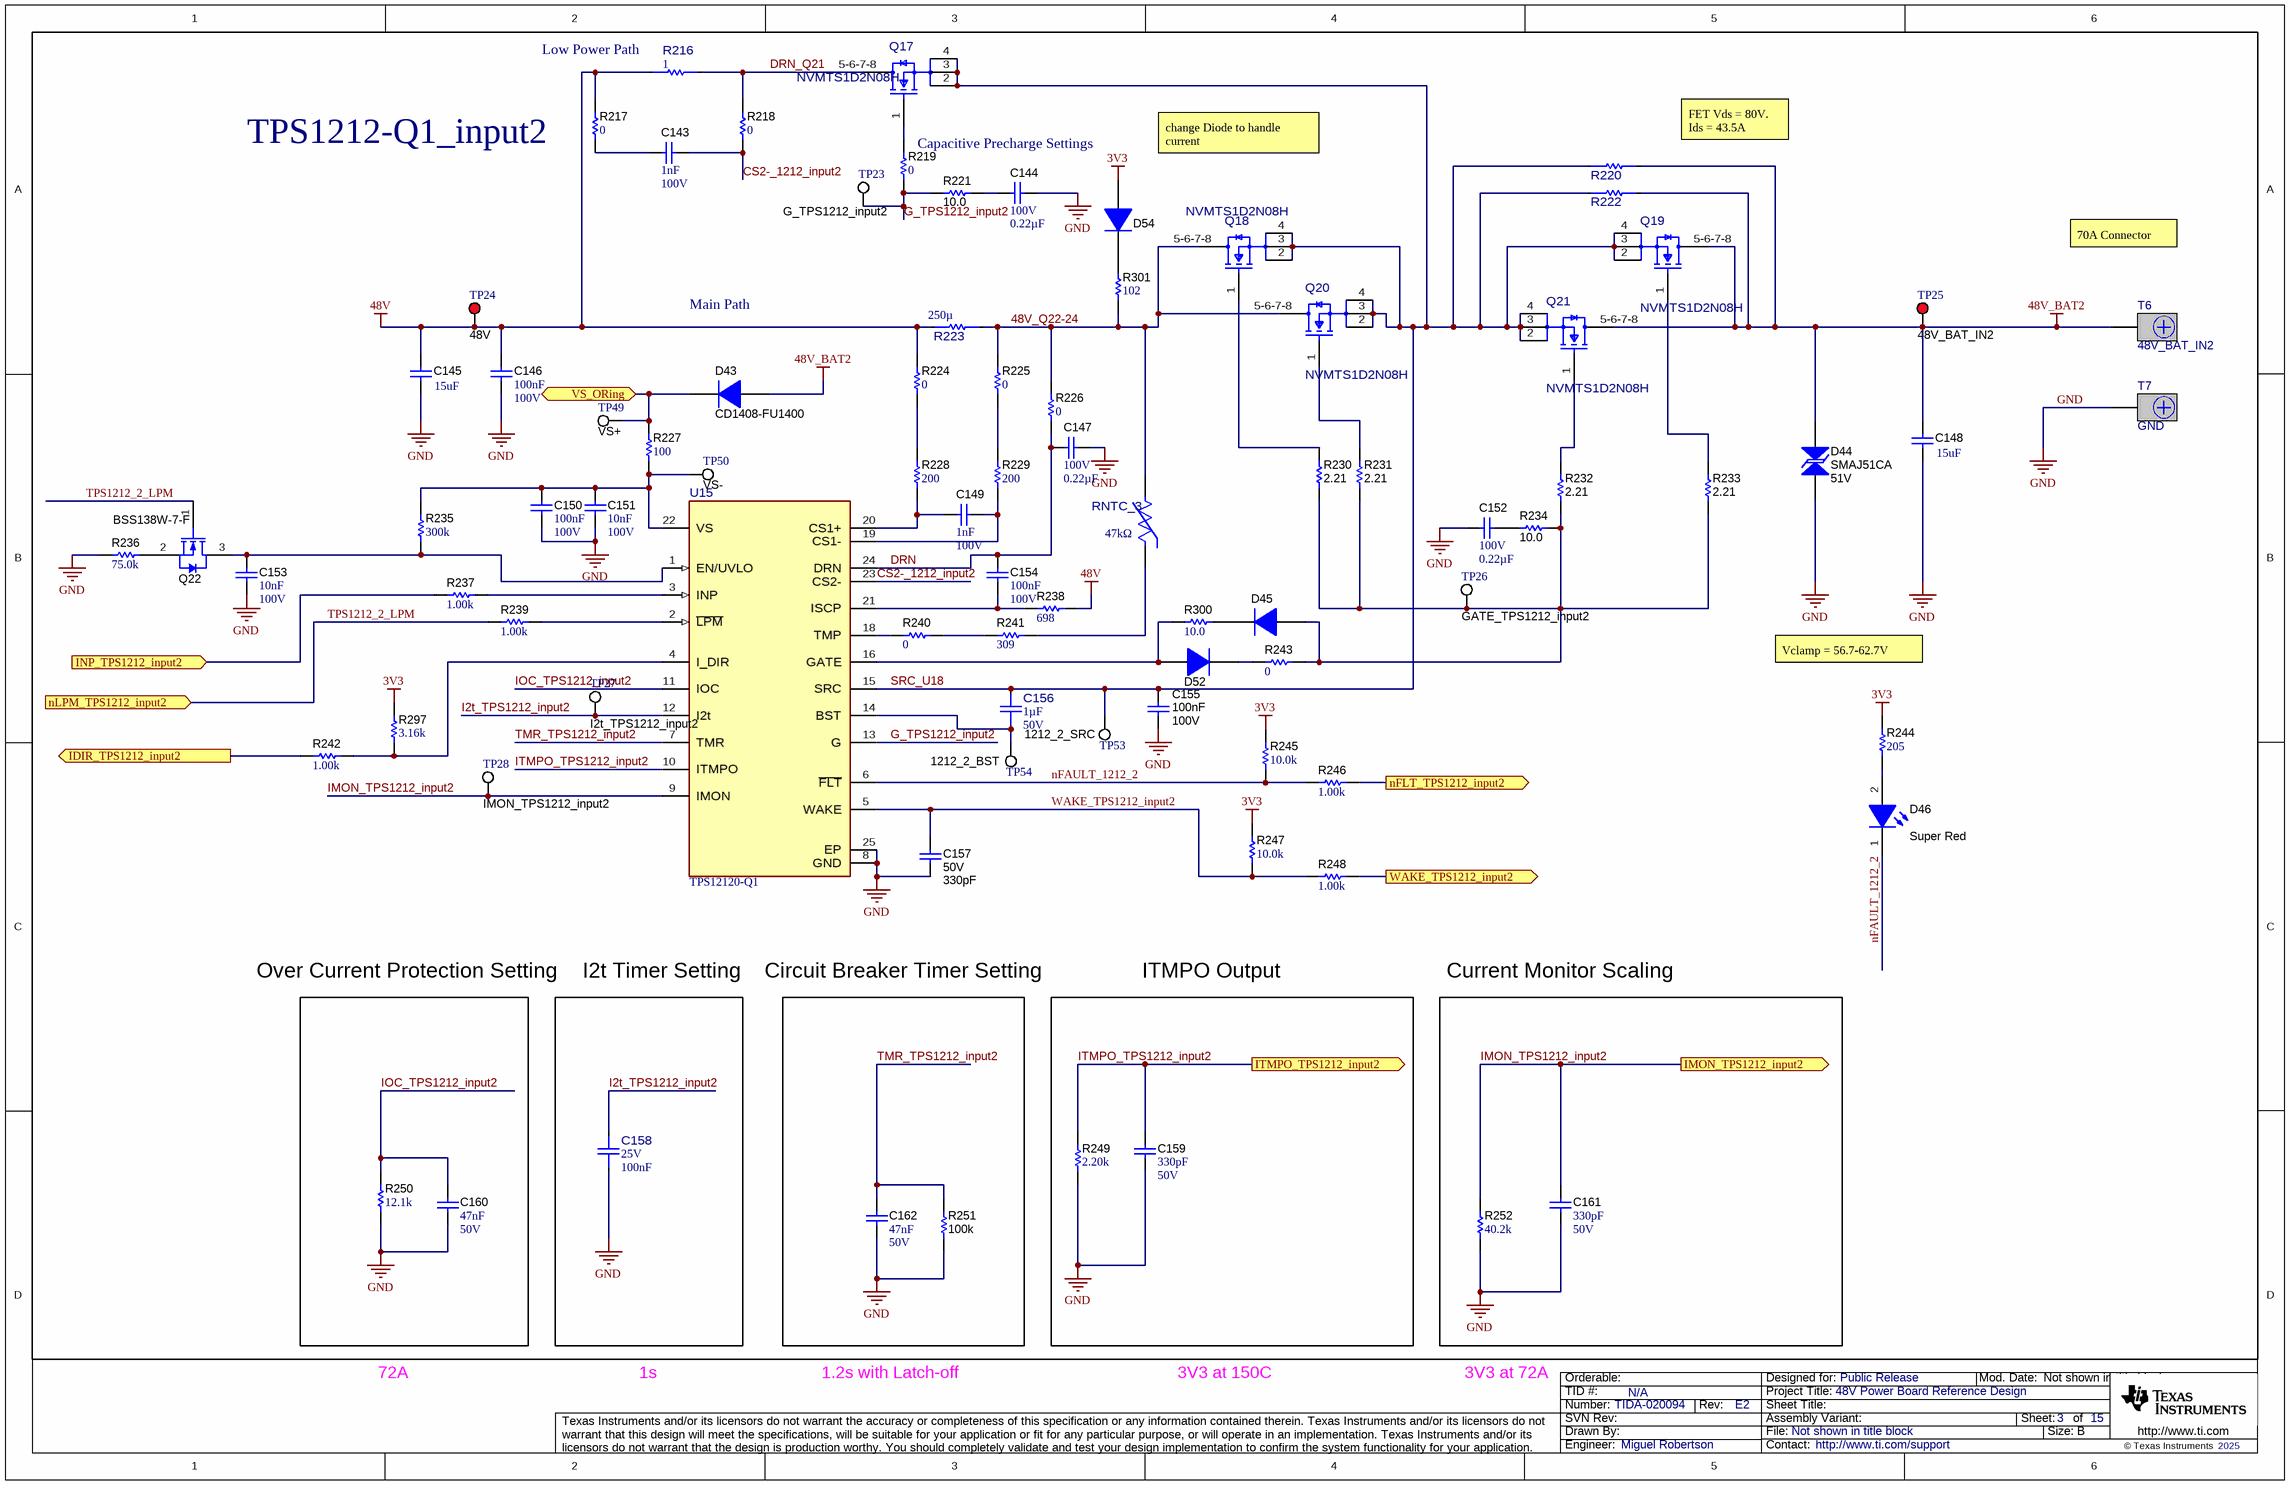
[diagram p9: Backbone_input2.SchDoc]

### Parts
C143  Cap_F: 1nF  VDC_V: 100V  [0603]  (hidden comment: CGA3E2X7R2A102K080AA)
C144  VDC_V: 100V  ValueDisplayed: 0.22µF  [0603]  (hidden comment: HMK107C7224MAHTE)
C145  ValueDisplayed: 15uF  [KCM55W]  (hidden comment: KCM55WR72A156MH01K)
C146  Cap_F: 100nF  VDC_V: 100V  [0603]  (hidden comment: HMK107B7104KAHT)
C147  VDC_V: 100V  ValueDisplayed: 0.22µF  [0603]  (hidden comment: HMK107C7224MAHTE)
C148  ValueDisplayed: 15uF  [KCM55W]  (hidden comment: KCM55WR72A156MH01K)
C149  Cap_F: 1nF  VDC_V: 100V  [0603]  (hidden comment: CGA3E2X7R2A102K080AA)
C150  Cap_F: 100nF  VDC_V: 100V  [0603]  (hidden comment: HMK107B7104KAHT)
C151  Cap_F: 10nF  VDC_V: 100V  [0603]  (hidden comment: CGA3E2X7R2A103K080AA)
C152  VDC_V: 100V  ValueDisplayed: 0.22µF  [0603]  (hidden comment: HMK107C7224MAHTE)
C153  Cap_F: 10nF  VDC_V: 100V  [0603]  (hidden comment: CGA3E2X7R2A103K080AA)
C154  Cap_F: 100nF  VDC_V: 100V  [0603]  (hidden comment: HMK107B7104KAHT)
C155  Cap_F: 100nF  VDC_V: 100V  [0805_HV]  (hidden comment: CGA4J2X7R2A104K125AA)
C156  Cap_F: 1µF  VDC_V: 50V  [FP-CL10B105KB9VPJC_0603-MFG]  (hidden comment: CL10B105KB9VPJC)
C157  VDC_V: 50V  ValueDisplayed: 330pF  [0402]  (hidden comment: GRM155R71H331KA01D)
C158  VDC_V: 25V  Cap_F: 100nF  [FP-GCJ188R71E104KA12D_0603-MFG]  (hidden comment: GCJ188R71E104KA12D)
C159  Cap_F: 330pF  VDC_V: 50V  [0603]  (hidden comment: C0603C331K5RACTU)
C160  Cap_F: 47nF  VDC_V: 50V  [0603]  (hidden comment: CGA3E2X7R1H473K080AA)
C161  Cap_F: 330pF  VDC_V: 50V  [0603]  (hidden comment: C0603C331K5RACTU)
C162  Cap_F: 47nF  VDC_V: 50V  [0603]  (hidden comment: CGA3E2X7R1H473K080AA)
D43  CD1408-FU1400  [Diode_1408]
D44  SMAJ51CA  value 51V  [SMA_Bi]
D45  1N4148W-TP  [SOD-123]  (value not drawn)
D46  value Super Red  [WL-SMCW_RED]  (hidden comment: 150060SS75000)
D52  1N4148W-TP  [SOD-123]  (value not drawn)
D54  1N4148W-TP  [SOD-123]  (value not drawn)
Q17  NVMTS1D2N08H  [FP-NVMTS1D2N08H_DFNW8-MFG]
Q18  NVMTS1D2N08H  [FP-NVMTS1D2N08H_DFNW8-MFG]
Q19  NVMTS1D2N08H  [FP-NVMTS1D2N08H_DFNW8-MFG]
Q20  NVMTS1D2N08H  [FP-NVMTS1D2N08H_DFNW8-MFG]
Q21  NVMTS1D2N08H  [FP-NVMTS1D2N08H_DFNW8-MFG]
Q22  BSS138W-7-F  [SOT-323]
R216  value 1  [FP-VMP-1R00-1.0-U_2010-MFG]  (hidden comment: VMP-1R00-1.0-U)
R217  ValueDisplayed: 0  [0603]  (hidden comment: CRCW06030000Z0EA)
R218  ValueDisplayed: 0  [0603]  (hidden comment: CRCW06030000Z0EA)
R219  ValueDisplayed: 0  [0603]  (hidden comment: CRCW06030000Z0EA)
R220  CSS2H-2512R-L500F  [FP-CSS2H-2512R-L500F_2512-MFG]  (value not drawn)
R221  ValueDisplayed: 10.0  [0805_HV]  (hidden comment: RC0805FR-0710RL)
R222  CSS2H-2512R-L500F  [FP-CSS2H-2512R-L500F_2512-MFG]  (value not drawn)
R223  value 250µ  [FP-HoLRS2512_2512-MFG]  (hidden comment: HoLRS2512-0.25mR-1%)
R224  ValueDisplayed: 0  [0603]  (hidden comment: CRCW06030000Z0EA)
R225  ValueDisplayed: 0  [0603]  (hidden comment: CRCW06030000Z0EA)
R226  ValueDisplayed: 0  [0603]  (hidden comment: CRCW06030000Z0EA)
R227  ValueDisplayed: 100  [0603]  (hidden comment: ERJ-3EKF1000V)
R228  ValueDisplayed: 200  [0603]  (hidden comment: RC0603FR-07200RL)
R229  ValueDisplayed: 200  [0603]  (hidden comment: RC0603FR-07200RL)
R230  ValueDisplayed: 2.21  [0603]  (hidden comment: RC0603FR-072R21L)
R231  ValueDisplayed: 2.21  [0603]  (hidden comment: RC0603FR-072R21L)
R232  ValueDisplayed: 2.21  [0603]  (hidden comment: RC0603FR-072R21L)
R233  ValueDisplayed: 2.21  [0603]  (hidden comment: RC0603FR-072R21L)
R234  ValueDisplayed: 10.0  [0805_HV]  (hidden comment: RC0805FR-0710RL)
R235  ValueDisplayed: 300k  [0603]  (hidden comment: RC0603FR-07300KL)
R236  ValueDisplayed: 75.0k  [0603]  (hidden comment: RC0603FR-0775KL)
R237  ValueDisplayed: 1.00k  [0603]  (hidden comment: RC0603FR-071KL)
R238  ValueDisplayed: 698  [0603]  (hidden comment: RC0603FR-07698RL)
R239  ValueDisplayed: 1.00k  [0603]  (hidden comment: RC0603FR-071KL)
R240  ValueDisplayed: 0  [0603]  (hidden comment: CRCW06030000Z0EA)
R241  ValueDisplayed: 309  [0603]  (hidden comment: RC0603FR-07309RL)
R242  ValueDisplayed: 1.00k  [0603]  (hidden comment: RC0603FR-071KL)
R243  ValueDisplayed: 0  [0603]  (hidden comment: CRCW06030000Z0EA)
R244  ValueDisplayed: 205  [0603]  (hidden comment: RC0603FR-07205RL)
R245  ValueDisplayed: 10.0k  [TNPW0603]  (hidden comment: TNPW060310K0BEEA)
R246  ValueDisplayed: 1.00k  [0603]  (hidden comment: RC0603FR-071KL)
R247  ValueDisplayed: 10.0k  [TNPW0603]  (hidden comment: TNPW060310K0BEEA)
R248  ValueDisplayed: 1.00k  [0603]  (hidden comment: RC0603FR-071KL)
R249  ValueDisplayed: 2.20k  [0603]  (hidden comment: RC0603FR-072K2L)
R250  ValueDisplayed: 12.1k  [0603]  (hidden comment: RC0603FR-0712K1L)
R251  ValueDisplayed: 100k  [0603]  (hidden comment: CRCW0603100KFKEA)
R252  ValueDisplayed: 40.2k  [0603]  (hidden comment: RC0603FR-0740K2L)
R297  ValueDisplayed: 3.16k  [0603]  (hidden comment: RC0603FR-073K16L)
R300  ValueDisplayed: 10.0  [0603]  (hidden comment: RC0603FR-0710RL)
R301  ValueDisplayed: 102  [0603]  (hidden comment: RC0603FR-07102RL)
RNTC_3  value 47kΩ  [FP-NCU18WB473J6SRB_0603-MFG]  (hidden comment: NCU18WB473J6SRB)
T6  48V_BAT_IN2  [Panduit_CXS70-14-C]
T7  GND  [Panduit_CXS70-14-C]
TP23  G_TPS1212_input2  [Keystone5012]
TP24  48V  [Keystone5010]
TP25  48V_BAT_IN2  [Keystone5010]
TP26  GATE_TPS1212_input2  [Keystone5012]
TP27  I2t_TPS1212_input2  [Keystone5012]
TP28  IMON_TPS1212_input2  [Keystone5012]
TP49  VS+  [Keystone5012]
TP50  VS-  [Keystone5012]
TP53  1212_2_SRC  [Keystone5012]
TP54  1212_2_BST  [Keystone5012]
U15  TPS12120-Q1  [RGE0023A-MFG]

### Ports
IDIR_TPS1212_input2 (out), IMON_TPS1212_input2 (out), INP_TPS1212_input2 (in), ITMPO_TPS1212_input2 (out), nFLT_TPS1212_input2 (out), nLPM_TPS1212_input2 (in), VS_ORing (bidir), WAKE_TPS1212_input2 (out)

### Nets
3V3: D54.2(A) R244.2 R245.2 R247.2 R297.2
48V: C145.1 C146.1 R216.1 R217.2 R223.1 R224.2 R238.2 TP24.1
48V_BAT2: C148.1 D43.2(A) D44.2 Q19.5-6-7-8(D) Q21.5-6-7-8(D) R220.2 R222.2 T6.1 TP25.1
GND: C144.1 C145.2 C146.2 C147.1 C148.2 C150.2 C151.2 C152.2 C153.2 C155.2 C157.2 C158.1 C159.2 C160.2 C161.2 C162.2 D44.1 R236.2 R249.1 R250.1 R251.1 R252.1 T7.1 U15.8(GND) U15.25(EP)
48V_Q22-24: Q18.5-6-7-8(D) Q20.5-6-7-8(D) R223.2 R225.2 R226.2 R301.1 RNTC_3.2  [project net 48V_Q22-24_3]
CS2-_1212_input2: C143.1 R218.1 U15.23(CS2-)  [project net CS2-_1212_input2_3]
DRN: C147.2 C154.1 R226.1 U15.24(DRN)  [project net DRN_3]
DRN_Q21: Q17.5-6-7-8(D) R216.2 R218.2  [project net DRN_Q21_3]
G_TPS1212_input2: R219.1 R221.2 TP23.1 U15.13(G)  [project net G_TPS1212_input2_3]
I2t_TPS1212_input2: C158.2 TP27.1 U15.12(I2t)  [project net I2t_TPS1212_input2_3]
IDIR_TPS1212_input2: R242.1 ; port IDIR_TPS1212_input2
IMON_TPS1212_input2: C161.1 R252.2 TP28.1 U15.9(IMON) ; port IMON_TPS1212_input2
INP_TPS1212_input2: R237.1 ; port INP_TPS1212_input2
IOC_TPS1212_input2: C160.1 R250.2 U15.11(IOC)  [project net IOC_TPS1212_input2_3]
ITMPO_TPS1212_input2: C159.1 R249.2 U15.10(ITMPO) ; port ITMPO_TPS1212_input2
nFAULT_1212_2: D46.1(K) R245.1 R246.1 U15.6(~{FLT})  [project net nFAULT_1212_2_3]
nFLT_TPS1212_input2: R246.2 ; port nFLT_TPS1212_input2
SRC_U18: C155.1 C156.2 Q17.2(S) Q17.3(S) Q17.4(S) Q18.2(S) Q18.3(S) Q18.4(S) Q19.2(S) Q19.3(S) Q19.4(S) Q20.2(S) Q20.3(S) Q20.4(S) Q21.2(S) Q21.3(S) Q21.4(S) R220.1 R222.1 TP53.1 U15.15(SRC)  [project net SRC_U18_3]
TMR_TPS1212_input2: C162.1 R251.2 U15.7(TMR)  [project net TMR_TPS1212_input2_3]
TPS1212_2_LPM: Q22.1(G) R239.1 ; port nLPM_TPS1212_input2  [project net nLPM_TPS1212_input2]
VS_ORing: D43.1(K) R227.2 TP49.1 ; port VS_ORing
WAKE_TPS1212_input2: C157.1 R247.1 R248.1 U15.5(WAKE)  [project net WAKE_TPS1212_input2_3]
WAKE_TPS1212_input2: R248.2 ; port WAKE_TPS1212_input2  [a separate net that carries the same name]
NetC143_2: C143.2 R217.1
NetC144_2: C144.2 R221.1
NetC149_1: C149.1 R229.1 U15.19(CS1-)
NetC149_2: C149.2 R228.1 U15.20(CS1+)
NetC150_1: C150.1 C151.1 R227.1 R235.2 TP50.1 U15.22(VS)
NetC152_1: C152.1 R234.1
NetC153_1: C153.1 Q22.3(D) R235.1 U15.1(EN/UVLO)
NetC154_2: C154.2 R238.1 U15.21(ISCP)
NetC156_1: C156.1 TP54.1 U15.14(BST)
NetD45_1: D45.1(K) R300.2
NetD45_2: D45.2(A) R230.1 R231.1 R232.1 R233.1 R234.2 R243.1 TP26.1
NetD46_2: D46.2(A) R244.1
NetD52_1: D52.1(K) R243.2
NetD52_2: D52.2(A) R300.1 U15.16(GATE)
NetD54_1: D54.1(K) R301.2
NetQ17_1: Q17.1(G) R219.2
NetQ18_1: Q18.1(G) R230.2
NetQ19_1: Q19.1(G) R233.2
NetQ20_1: Q20.1(G) R231.2
NetQ21_1: Q21.1(G) R232.2
NetQ22_2: Q22.2(S) R236.1
NetR224_1: R224.1 R228.2
NetR225_1: R225.1 R229.2
NetR237_2: R237.2 U15.3(INP)
NetR239_2: R239.2 U15.2(~{LPM})
NetR240_1: R240.1 R241.1
NetR240_2: R240.2 U15.18(TMP)
NetR241_2: R241.2 RNTC_3.1
NetR242_2: R242.2 R297.1 U15.4(I_DIR)

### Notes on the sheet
- (near R216) Low Power Path
- (near R217) TPS1212-Q1_input2
- (near R219) Capacitive Precharge Settings
- change Diode to handle current
- FET Vds = 80V. Ids = 43.5A
- 70A Connector
- Main Path
- Vclamp = 56.7-62.7V
- Over Current Protection Setting
- I2t Timer Setting
- Circuit Breaker Timer Setting
- ITMPO Output
- Current Monitor Scaling
- 72A
- 1s
- 1.2s with Latch-off
- 3V3 at 150C
- 3V3 at 72A

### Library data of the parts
C143 C149 = CMP-0007081-4: as C79 on sheet 12V E-Fuse
C144 C147 C152 = CMP-0077895-3: CAP, CERM, 0.22 µF, 100 V,+/- 20%, X7S, AEC-Q200 Grade 1, 0603; Manufacturer: Taiyo Yuden; TaMin_C: -55°C; Polarized: N; SizeAreaWB_mm2: 4.68; U/M: EA; Value: 0.22uF; TaMax_C: 125°C; SizeZ_mm: 1.0; SizeX_mm: 1.6; SizeY_mm: 0.8; SizeArea_mm2: 1.28; AEC Qualified: Y; Cap_F: 220nF; AEC Grade: 1; AEC Category: Q200
C145 C148 = CMP-0009477-2: CAP, CERM, 15 uF, 100 V, +/- 20%, X7R, Stacked 2220; Manufacturer: MuRata; TaMin_C: -55°C; Polarized: N; SizeAreaWB_mm2: 59.13; Value1: Unknown; U/M: EA; Value: 15uF; TaMax_C: 125°C; SizeZ_mm: 6.7; SizeX_mm: 6.1; SizeY_mm: 5.3; Cap_Case: 2220; Value2: 100V; SizeArea_mm2: 32.33; Cap_F: 15µF; AEC Category: Q200
C146 C150 C154 = CMP-0081011-1: CAP, CERM, 0.1 µF, 100 V,+/- 10%, X7R, AEC-Q200 Grade 1, 0603; Manufacturer: Taiyo Yuden; SizeAreaWB_mm2: 4.68; SizeArea_mm2: 1.28; AEC Qualified: Y; AEC Category: Q200; Value: 0.1uF; TaMax_C: 125°C; SizeZ_mm: 1; Polarized: N; TaMin_C: -55°C; SizeY_mm: 0.8; U/M: EA; SizeX_mm: 1.6; ValueDisplayed: 0.1µF
C151 C153 = CMP-0007082-4: CAP, CERM, 0.01 uF, 100 V, +/- 10%, X7R, AEC-Q200 Grade 1, 0603; Manufacturer: TDK; TaMin_C: -55°C; ESR_ohm: 0.2354; Polarized: N; SizeAreaWB_mm2: 4.68; Value1: 0.235428 ohm; U/M: EA; Value: 0.01uF; TaMax_C: 125°C; SizeZ_mm: 1; SizeX_mm: 1.6; SizeY_mm: 0.8; SizeArea_mm2: 1.28; AEC Qualified: Y; IRMS_A: 396.995mA; AEC Category: Q200
C155 = CMP-0007969-2: CAP, CERM, 0.1 uF, 100 V, +/- 10%, X7R, AEC-Q200 Grade 1, 0805; Manufacturer: TDK; TaMin_C: -55°C; ESR_ohm: 0.020726; Polarized: N; SizeAreaWB_mm2: 6.75; Value1: 0.020726 ohm; U/M: EA; Value: 0.1uF; TaMax_C: 125°C; SizeZ_mm: 1.45; SizeX_mm: 2; SizeY_mm: 1.25; Cap_Case: 0805; SizeArea_mm2: 2.5; AEC Qualified: Y; IRMS_A: 1.456A; AEC Grade: 1; AEC Category: Q200
C156 = CMP-0122257-1: as C7 on sheet Motor Drivers
C157 = CMP-0006687-2: CAP, CERM, 330 pF, 50 V, +/- 10%, X7R, 0402; Manufacturer: MuRata; TaMin_C: -55°C; Polarized: N; SizeAreaWB_mm2: 3; Value1: Unknown; U/M: EA; Value: 330pF; TaMax_C: 125°C; SizeZ_mm: 0.6; SizeX_mm: 1; SizeY_mm: 0.5; AEC Category: Q200
C158 = CMP-0095670-2: Cap Ceramic 0.1uF 25V X7R 10% Pad SMD 0603 Soft Termination +125°C Automotive T/R; Manufacturer: Murata; Value: 100nF; AEC Qualified: Yes; AEC Grade: Grade 1; SizeZ_mm: 0.9mm; TempCo: 15%
C159 C161 = CMP-0006921-4: CAP, CERM, 330 pF, 50 V, +/- 10%, X7R, 0603; Manufacturer: Kemet; TaMin_C: -55°C; Polarized: N; SizeAreaWB_mm2: 4.68; Value1: Unknown; U/M: EA; Value: 330pF; TaMax_C: 125°C; SizeZ_mm: 1; SizeX_mm: 1.6; SizeY_mm: 0.8; SizeArea_mm2: 1.28; AEC Category: Q200
C160 C162 = CMP-0007079-4: CAP, CERM, 0.047 uF, 50 V, +/- 10%, X7R, AEC-Q200 Grade 1, 0603; Manufacturer: TDK; TaMin_C: -55°C; ESR_ohm: 49.007m; Polarized: N; SizeAreaWB_mm2: 4.68; Value1: 0.049007 ohm; U/M: EA; TaMax_C: 125°C; SizeZ_mm: 1; SizeX_mm: 1.6; SizeY_mm: 0.8; SizeArea_mm2: 1.28; AEC Qualified: Y; IRMS_A: 767.528mA; AEC Category: Q200
D43 = CMP-0029014-2: Diode, Ultrafast, 400 V, 1 A, 1408 Diode; Manufacturer: Bourns; SizeAreaWB_mm2: 12.76; SizeZ_mm: 1.15; Value2: 1.05V; Green_REACh: Incomplete; SizeY_mm: 1.9; Value: 400V; TJmax_C: 150°C; Io_A: 1A; AEC Category: Q101; RJC_CperW: 40; SizeX_mm: 3.4; SizeArea_mm2: 6.46; Green_Lifecycle: Not Set
D44 = CMP-0085022-1: Diode, TVS, Bi, 51 V, 82.4 Vc, 400 W, 4.9 A, SMA (non-polarized); Manufacturer: Littelfuse; AEC Qualified: N; SizeZ_mm: 2.65; AEC Category: Q101; RJA_CperW: 120; SizeX_mm: 5.075; Vc: 82.4V; SizeY_mm: 2.575; Vbr_Max: 62.7V; Vbr_Min: 56.7V; Ppk: 400W; Ipp: 4.9A; SizeAreaWB_mm2: 32.368125; SizeArea_mm2: 13.068125
D45 D52 D54 = CMP-0076974-1: Diode, Switching, 100 V, 0.15 A, SOD-123; Manufacturer: Micro Commercial Components; SizeAreaWB_mm2: 13.095; Vr_V: 100V; SizeArea_mm2: 6.545; TJmax_C: 150°C; AEC Category: Q101; Value: 100V; SizeZ_mm: 1.35; Green_REACh: Incomplete; Io_A: 150mA; Vf_V: 1.25V; SizeY_mm: 1.7; Green_Lifecycle: Not Set; U/M: EA; Value1: 0.15A; SizeX_mm: 3.85
D46 = CMP-0002893-1: as D3 on sheet Motor Drivers
Q17-Q21 = CMP-0088066-1: N-Channel Power MOSFET 80V 3374A 1.1mOhm 8-Pin DFNW Surface Mount T/R; Manufacturer: ON Semiconductor; IdsMax_A: 43.5A; Vgs_V: 20V; AEC Qualified: Yes; ChMode: False; QgTyp_nC: 147nC @ 10V; SizeZ_mm: 1.2mm; Rdson45_ohm: 930µ
Q22 = CMP-0000757-1: MOSFET, N-CH, 50 V, 0.2 A, SOT-323; Alternate Manufacturer: None; Manufacturer: Diodes Inc.; SizeZ_mm: 1.1; ChType: N; Value1: 3; VdsMax_V: 50V; SizeX_mm: 2.2; Vgs_V: 1.5V; Value: 50V; Rdson45_ohm: 3.5; SizeArea_mm2: 4.84; AEC Category: Q101; IdsMax_A: 200mA; SizeAreaWB_mm2: 10.24; U/M: EA
R216 = CMP-0098465-1: 1 Ohms ±1% 3W Chip Resistor 2010 (5025 Metric) Automotive AEC-Q200, Current Sense, Moisture Resistant, Pulse Withstanding; Manufacturer: Isabellenhuette; AEC Grade: Grade 0; AEC Qualified: Yes; SizeZ_mm: 0.55mm; TempCo: 20ppm/°C
R217-R219 R224-R226 R240 R243 = CMP-0025697-4: RES, 0, 5%, 0.1 W, AEC-Q200 Grade 0, 0603; Manufacturer: Vishay-Dale; Power_W: 100mW; TempCo: 200 ppm/C; Value_Code: 0000; Value: 0; EIA_Code: E24; SizeX_mm: 1.6; SizeY_mm: 0.8; SizeZ_mm: 1; Value2: 0.1W; SizeArea_mm2: 1.28; CompType: Resistor; AEC Qualified: Y; VDC_V: 75V; AEC Category: Q200
R220 R222 = CMP-0095938-1: 500 µOhms ±1% 6W Chip Resistor 2512 (6432 Metric) Automotive AEC-Q200, Current Sense Metal Element; Manufacturer: Bourns; AEC Qualified: Yes; Standoff Height: 0.15mm; SizeZ_mm: 1.23mm; Value: 500µ; TempCo: 100ppm/°C; AEC Grade: Grade 0
R221 R234 = CMP-0021863-2: RES, 10.0, 1%, 0.125 W, 0805; Manufacturer: Yageo America; Power_W: 125mW; TempCo: 200 ppm/C; Value_Code: 10R0; U/M: EA; Value: 10.0; EIA_Code: E96; Res_ohm: 10; SizeX_mm: 2; SizeY_mm: 1.25; SizeZ_mm: 1.45; Value2: 0.125W; SizeArea_mm2: 2.5; VDC_V: 150V; AEC Category: Q200
R223 = CMP-0124268-3: 0.25 mOhms ±1% 3W Chip Resistor 2512 (6332 Metric) Automotive AEC-Q200, Current Sense Metal Element; Manufacturer: Shenzhen Milliohm Electronic; AEC Grade: Grade 0; AEC Qualified: Yes; SizeZ_mm: 1.9mm; TempCo: 50ppm/°C
R227 = CMP-0022679-3: RES, 100, 1%, 0.1 W, AEC-Q200 Grade 0, 0603; Manufacturer: Panasonic; Power_W: 100mW; TempCo: 100 ppm/C; Value_Code: 100R; U/M: EA; Value: 100; EIA_Code: E96; SizeX_mm: 1.6; SizeY_mm: 0.8; SizeZ_mm: 1; Value2: 0.1W; SizeArea_mm2: 1.28; AEC Qualified: Y; AEC Grade: 0; AEC Category: Q200
R228 R229 = CMP-0022902-5: RES, 200, 1%, 0.1 W, 0603; Manufacturer: Yageo; Power_W: 100mW; TempCo: 100 ppm/C; Value_Code: 200R; Value: 200; EIA_Code: E96; SizeX_mm: 1.6; SizeY_mm: 0.8; SizeZ_mm: 1; Value2: 0.1W; SizeArea_mm2: 1.28; AEC Qualified: N; VDC_V: 75V; AEC Category: Q200; SizeAreaWB_mm2: 4.68
R230-R233 = CMP-0023007-4: RES, 2.21, 1%, 0.1 W, 0603; Manufacturer: Yageo; Power_W: 100mW; TempCo: 200 ppm/C; Value_Code: 2R21; Value: 2.21; EIA_Code: E96; SizeX_mm: 1.6; SizeY_mm: 0.8; SizeZ_mm: 1; Value2: 0.1W; SizeArea_mm2: 1.28; AEC Qualified: N; VDC_V: 75V; AEC Category: Q200; SizeAreaWB_mm2: 4.68
R235 = CMP-0023012-4: RES, 300 k, 1%, 0.1 W, 0603; Manufacturer: Yageo; Power_W: 100mW; TempCo: 100 ppm/C; Value: 300k; SizeX_mm: 1.6; SizeY_mm: 0.8; SizeZ_mm: 1; Value2: 0.1W; SizeArea_mm2: 1.28; AEC Qualified: N; VDC_V: 75V; AEC Category: Q200; SizeAreaWB_mm2: 4.68
R236 = CMP-0023267-5: RES, 75.0 k, 1%, 0.1 W, 0603; Manufacturer: Yageo; Power_W: 100mW; TempCo: 100 ppm/C; Value_Code: 75k0; Value: 75.0k; EIA_Code: E96; Res_ohm: 75k; SizeX_mm: 1.6; SizeY_mm: 0.8; SizeZ_mm: 1; Value2: 0.1W; SizeArea_mm2: 1.28; AEC Qualified: N; VDC_V: 75V; AEC Category: Q200; SizeAreaWB_mm2: 4.68
R237 R239 R242 R246 R248 = CMP-0022895-5: as R14 on sheet Motor Drivers
R238 = CMP-0023243-5: as R73 on sheet 12V E-Fuse
R241 = CMP-0023017-5: RES, 309, 1%, 0.1 W, 0603; Manufacturer: Yageo; Power_W: 100mW; TempCo: 100 ppm/C; Value_Code: 309R; Value: 309; EIA_Code: E96; SizeX_mm: 1.6; SizeY_mm: 0.8; SizeZ_mm: 1; Value2: 0.1W; SizeArea_mm2: 1.28; AEC Qualified: N; VDC_V: 75V; AEC Category: Q200; SizeAreaWB_mm2: 4.68
R244 = CMP-0022904-5: as R3 on sheet Motor Drivers
R245 R247 = CMP-0025686-1: RES, 10.0 k, 0.1%, 0.1 W, AEC-Q200 Grade 1, 0603; Manufacturer: Vishay-Dale; Power_W: 100mW; TempCo: 25 ppm/C; Value_Code: 10k0; U/M: EA; Value: 10.0k; EIA_Code: E192; Res_ohm: 10k; SizeX_mm: 1.6; SizeY_mm: 0.85; SizeZ_mm: 0.55; Value2: 0.1W; SizeArea_mm2: 1.36; AEC Qualified: Y; VDC_V: 75V; AEC Grade: 1; AEC Category: Q200
R249 = CMP-0022986-5: RES, 2.20 k, 1%, 0.1 W, 0603; Manufacturer: Yageo; Power_W: 100mW; TempCo: 100 ppm/C; Value_Code: 2k20; Value: 2.20k; Res_ohm: 2.2k; SizeX_mm: 1.6; SizeY_mm: 0.8; SizeZ_mm: 1; Value2: 0.1W; SizeArea_mm2: 1.28; AEC Qualified: N; VDC_V: 75V; AEC Category: Q200; SizeAreaWB_mm2: 4.68
R250 = CMP-0022776-5: RES, 12.1 k, 1%, 0.1 W, 0603; Manufacturer: Yageo; Power_W: 100mW; TempCo: 100 ppm/C; Value_Code: 12k1; Value: 12.1k; EIA_Code: E96; SizeX_mm: 1.6; SizeY_mm: 0.8; SizeZ_mm: 1; Value2: 0.1W; SizeArea_mm2: 1.28; AEC Qualified: N; VDC_V: 75V; AEC Category: Q200; SizeAreaWB_mm2: 4.68
R251 = CMP-0021990-4: RES, 100 k, 1%, 0.1 W, AEC-Q200 Grade 0, 0603; Manufacturer: Vishay-Dale; Power_W: 100mW; TempCo: 100 ppm/C; Value: 100k; EIA_Code: E96; SizeX_mm: 1.6; SizeY_mm: 0.8; SizeZ_mm: 1; Value2: 0.1W; SizeArea_mm2: 1.28; AEC Qualified: Y; VDC_V: 75V; AEC Category: Q200; AEC Grade: 0
R252 = CMP-0023098-5: RES, 40.2 k, 1%, 0.1 W, 0603; Manufacturer: Yageo; Power_W: 100mW; TempCo: 100 ppm/C; Value_Code: 40k2; Value: 40.2k; EIA_Code: E96; SizeX_mm: 1.6; SizeY_mm: 0.8; SizeZ_mm: 1; Value2: 0.1W; SizeArea_mm2: 1.28; AEC Qualified: N; VDC_V: 75V; AEC Category: Q200; SizeAreaWB_mm2: 4.68
R297 = CMP-0023078-5: RES, 3.16 k, 1%, 0.1 W, 0603; Manufacturer: Yageo; Power_W: 100mW; TempCo: 100 ppm/C; Value_Code: 3k16; Value: 3.16k; EIA_Code: E96; SizeX_mm: 1.6; SizeY_mm: 0.8; SizeZ_mm: 1; Value2: 0.1W; SizeArea_mm2: 1.28; AEC Qualified: N; VDC_V: 75V; AEC Category: Q200; SizeAreaWB_mm2: 4.68
R300 = CMP-0022751-4: as R63 on sheet 12V E-Fuse
R301 = CMP-0022738-5: RES, 102, 1%, 0.1 W, 0603; Manufacturer: Yageo; Power_W: 100mW; TempCo: 100 ppm/C; Value_Code: 102R; Value: 102; EIA_Code: E96; SizeX_mm: 1.6; SizeY_mm: 0.8; SizeZ_mm: 1; Value2: 0.1W; SizeArea_mm2: 1.28; AEC Qualified: N; VDC_V: 75V; AEC Category: Q200; SizeAreaWB_mm2: 4.68
RNTC_3 = CMP-0095715-1: NTC Thermistor for Temperature Sensor, Automotive, 0603, 47kΩ, 5%, 0.046mA, 5V; Manufacturer: Murata; B 25 50: 4050K; B 25 100: 4131K; SizeZ_mm: 0.95mm; AEC Qualified: Yes; B 25 85: 4108K; B Tolerance: 1%; Automotive Grade: Grade 0
T6 T7 = CMP-0075010-2: Terminal 70A Lug; PartNumber: CXS70-14-C; Manufacturer: Panduit; CompType: Screw Terminal; CT: False; Green_Lifecycle: Not Set; Green_REACh: Incomplete
TP23 TP26-TP28 TP49 TP50 TP53 TP54 = CMP-0055149-1: as TP41-TP44 on sheet 12V E-Fuse
TP24 TP25 = CMP-0055147-2: as TP1-TP3 on sheet Motor Drivers
U15 = CMP-0124371-1: Low IQ Automotive High Side Switch Controller with Bi-directional IMON, Low Power Mode, Load Wakeup, I2t and Diagnostics; Manufacturer: Texas Instruments; SizeZ_mm: 1mm; AEC Qualified: No; AEC Grade: Grade 1; Max Supply Voltage: 73V; Min Supply Voltage: 3.5V; Number Of Outputs: 1; Standoff Height: 0mm; TJmax_C: +150°C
